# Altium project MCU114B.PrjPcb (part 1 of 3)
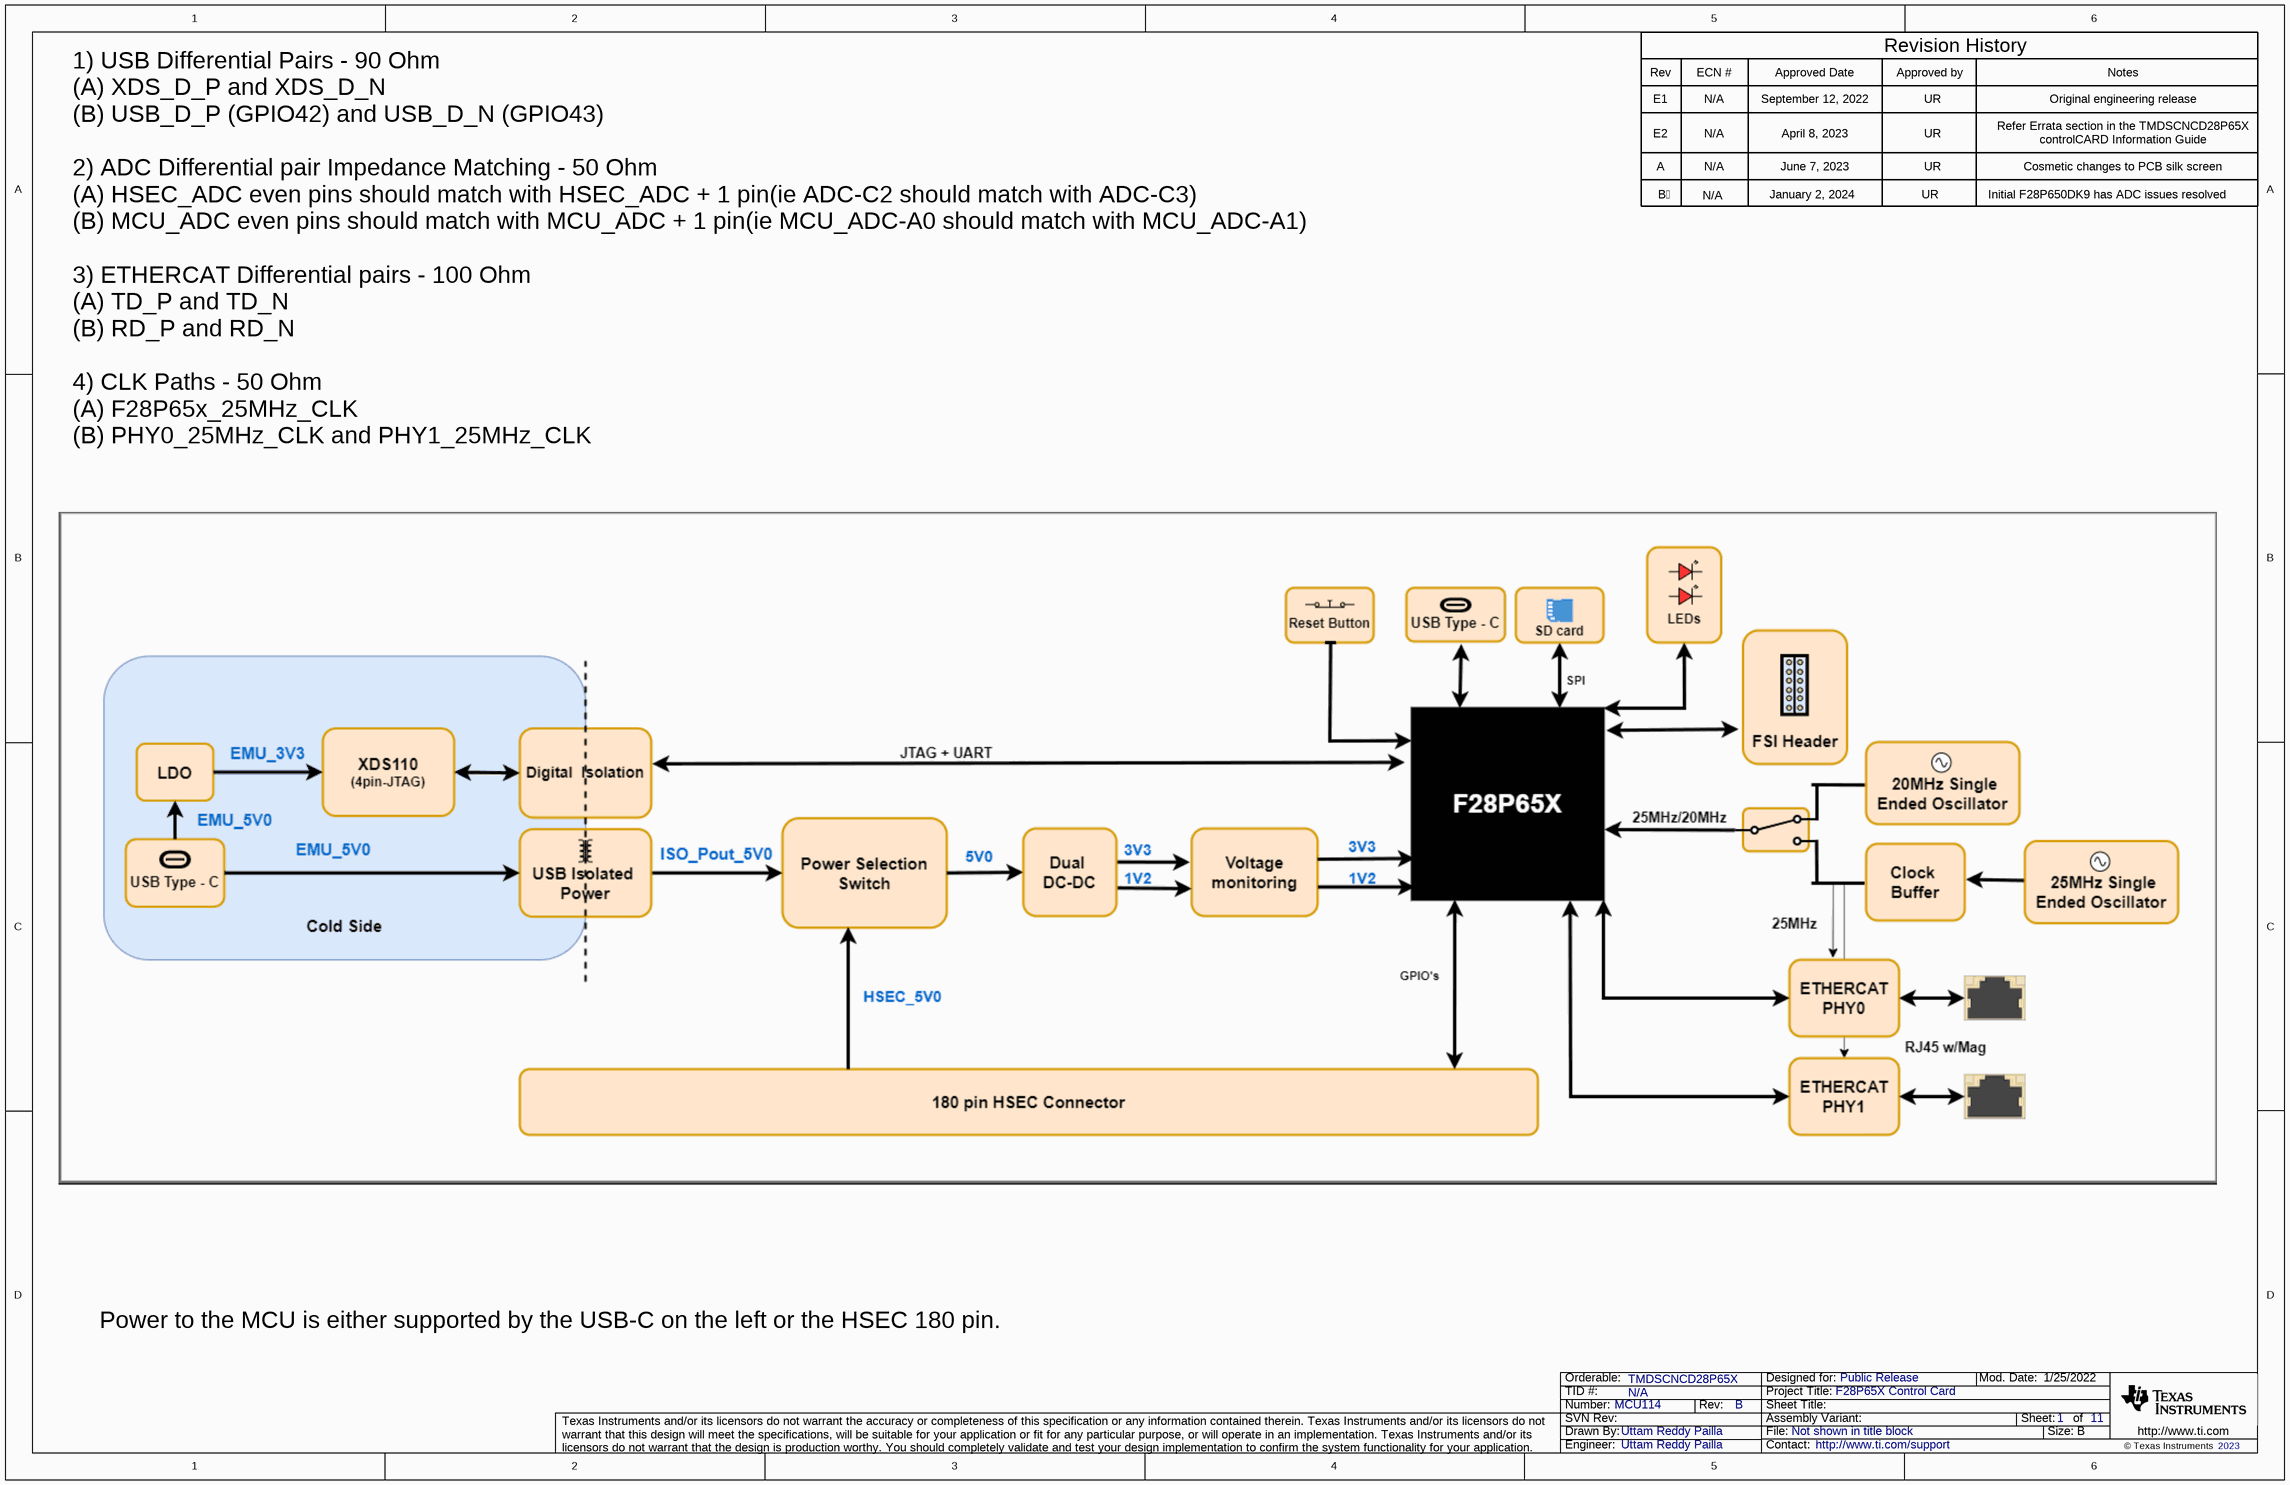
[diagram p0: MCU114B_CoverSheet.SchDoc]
CopyrightYear: 2023; DrawnBy: Uttam Reddy Pailla; EVM_orderable: TMDSCNCD28P65X; PCB_Layout: Uttam Reddy Pailla; PCB_Rev: B; PRJ_Customer: Public Release; PRJ_Engineer: Uttam Reddy Pailla; PRJ_Number: MCU114; PRJ_Title: F28P65X Control Card; SCH_Rev: B; TechSupport: http://www.ti.com/support; TID: N/A
11 sheets, 445 parts. Net scope: global (net labels, ports and power ports of the same name join across sheets).
Board file: MCU114B.PcbDoc
Sheets:
  MCU114B_CoverSheet.SchDoc
  MCU114B_GPIOs.SchDoc
  MCU114B_Support.SchDoc
  MCU114B_ADC.SchDoc
  MCU114B_Power.SchDoc
  MCU114B_EtherCAT.SchDoc
  MCU114B_USB.SchDoc
  MCU114B_XDS110_USB_Power.SchDoc
  MCU114B_XDS110_MCU.SchDoc
  MCU114B_Emulator_Interface.SchDoc
  MCU114B_EVM_Hardware.SchDoc

## Sheet MCU114B_CoverSheet.SchDoc
size 431 x 279 mm; Date: Not shown in title block; ApprovedBy: Not shown in title block; CheckedBy: Not shown in title block; Author: Not shown in title block; CompanyName: Not shown in title block; Engineer: Not shown in title block; Organization: Not shown in title block; Address1: Not shown in title block; Address2: Not shown in title block; Address3: Not shown in title block; Address4: Not shown in title block; DocumentNumber: 1; Revision: Use project parameter SCH_Rev; SheetNumber: 1; SheetTotal: 11; PageSetup: Record=PageOptions¦CenterHorizontal=True¦CenterVertical=True¦PrintScale=1.00¦XCorrection=1.00¦YCorrection=1.00¦PrintKind=0¦BorderSize=5000000¦LeftOffset=0¦BottomOffset=0¦Orientation=2¦PaperLength=1000¦PaperWidth=1000¦Scale=100¦PaperSource=15¦PrintQuality=600¦MediaType=1¦DitherType=10¦PaperKind=Letter¦PrintScaleMode=1

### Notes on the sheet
- Rev
- E1
- ECN #
- N/A
- Approved Date
- September 12, 2022
- Approved by
- UR
- Revision History
- Notes
- Original engineering release
- E2
- A
- April 8, 2023
- June 7, 2023
- Refer Errata section in the TMDSCNCD28P65X
- controlCARD Information Guide
- Cosmetic changes to PCB silk screen
- B
- January 2, 2024
- Initial F28P650DK9 has ADC issues resolved
- 1) USB Differential Pairs - 90 Ohm
  (A) XDS_D_P and XDS_D_N
  (B) USB_D_P (GPIO42) and USB_D_N (GPIO43)
  2) ADC Differential pair Impedance Matching - 50 Ohm
  (A) HSEC_ADC even pins should match with HSEC_ADC + 1 pin(ie ADC-C2 should match with ADC-C3)
  (B) MCU_ADC even pins should match with MCU_ADC + 1 pin(ie MCU_ADC-A0 should match with MCU_ADC-A1)
  3) ETHERCAT Differential pairs - 100 Ohm
  (A) TD_P and TD_N
  (B) RD_P and RD_N
  4) CLK Paths - 50 Ohm
  (A) F28P65x_25MHz_CLK
  (B) PHY0_25MHz_CLK and PHY1_25MHz_CLK
- Power to the MCU is either supported by the USB-C on the left or the HSEC 180 pin.

## Sheet MCU114B_GPIOs.SchDoc
size 431 x 279 mm; Date: Not shown in title block; ApprovedBy: Not shown in title block; CheckedBy: Not shown in title block; Author: Not shown in title block; CompanyName: Not shown in title block; Engineer: Not shown in title block; Organization: Not shown in title block; Address1: Not shown in title block; Address2: Not shown in title block; Address3: Not shown in title block; Address4: Not shown in title block; DocumentNumber: 2; Revision: Use project parameter SCH_Rev; SheetNumber: 2; SheetTotal: 11; PageSetup: Record=PageOptions¦CenterHorizontal=True¦CenterVertical=True¦PrintScale=1.00¦XCorrection=1.00¦YCorrection=1.00¦PrintKind=0¦BorderSize=5000000¦LeftOffset=0¦BottomOffset=0¦Orientation=2¦PaperLength=1000¦PaperWidth=1000¦Scale=100¦PaperSource=15¦PrintQuality=600¦MediaType=1¦DitherType=10¦PaperKind=Letter¦PrintScaleMode=1
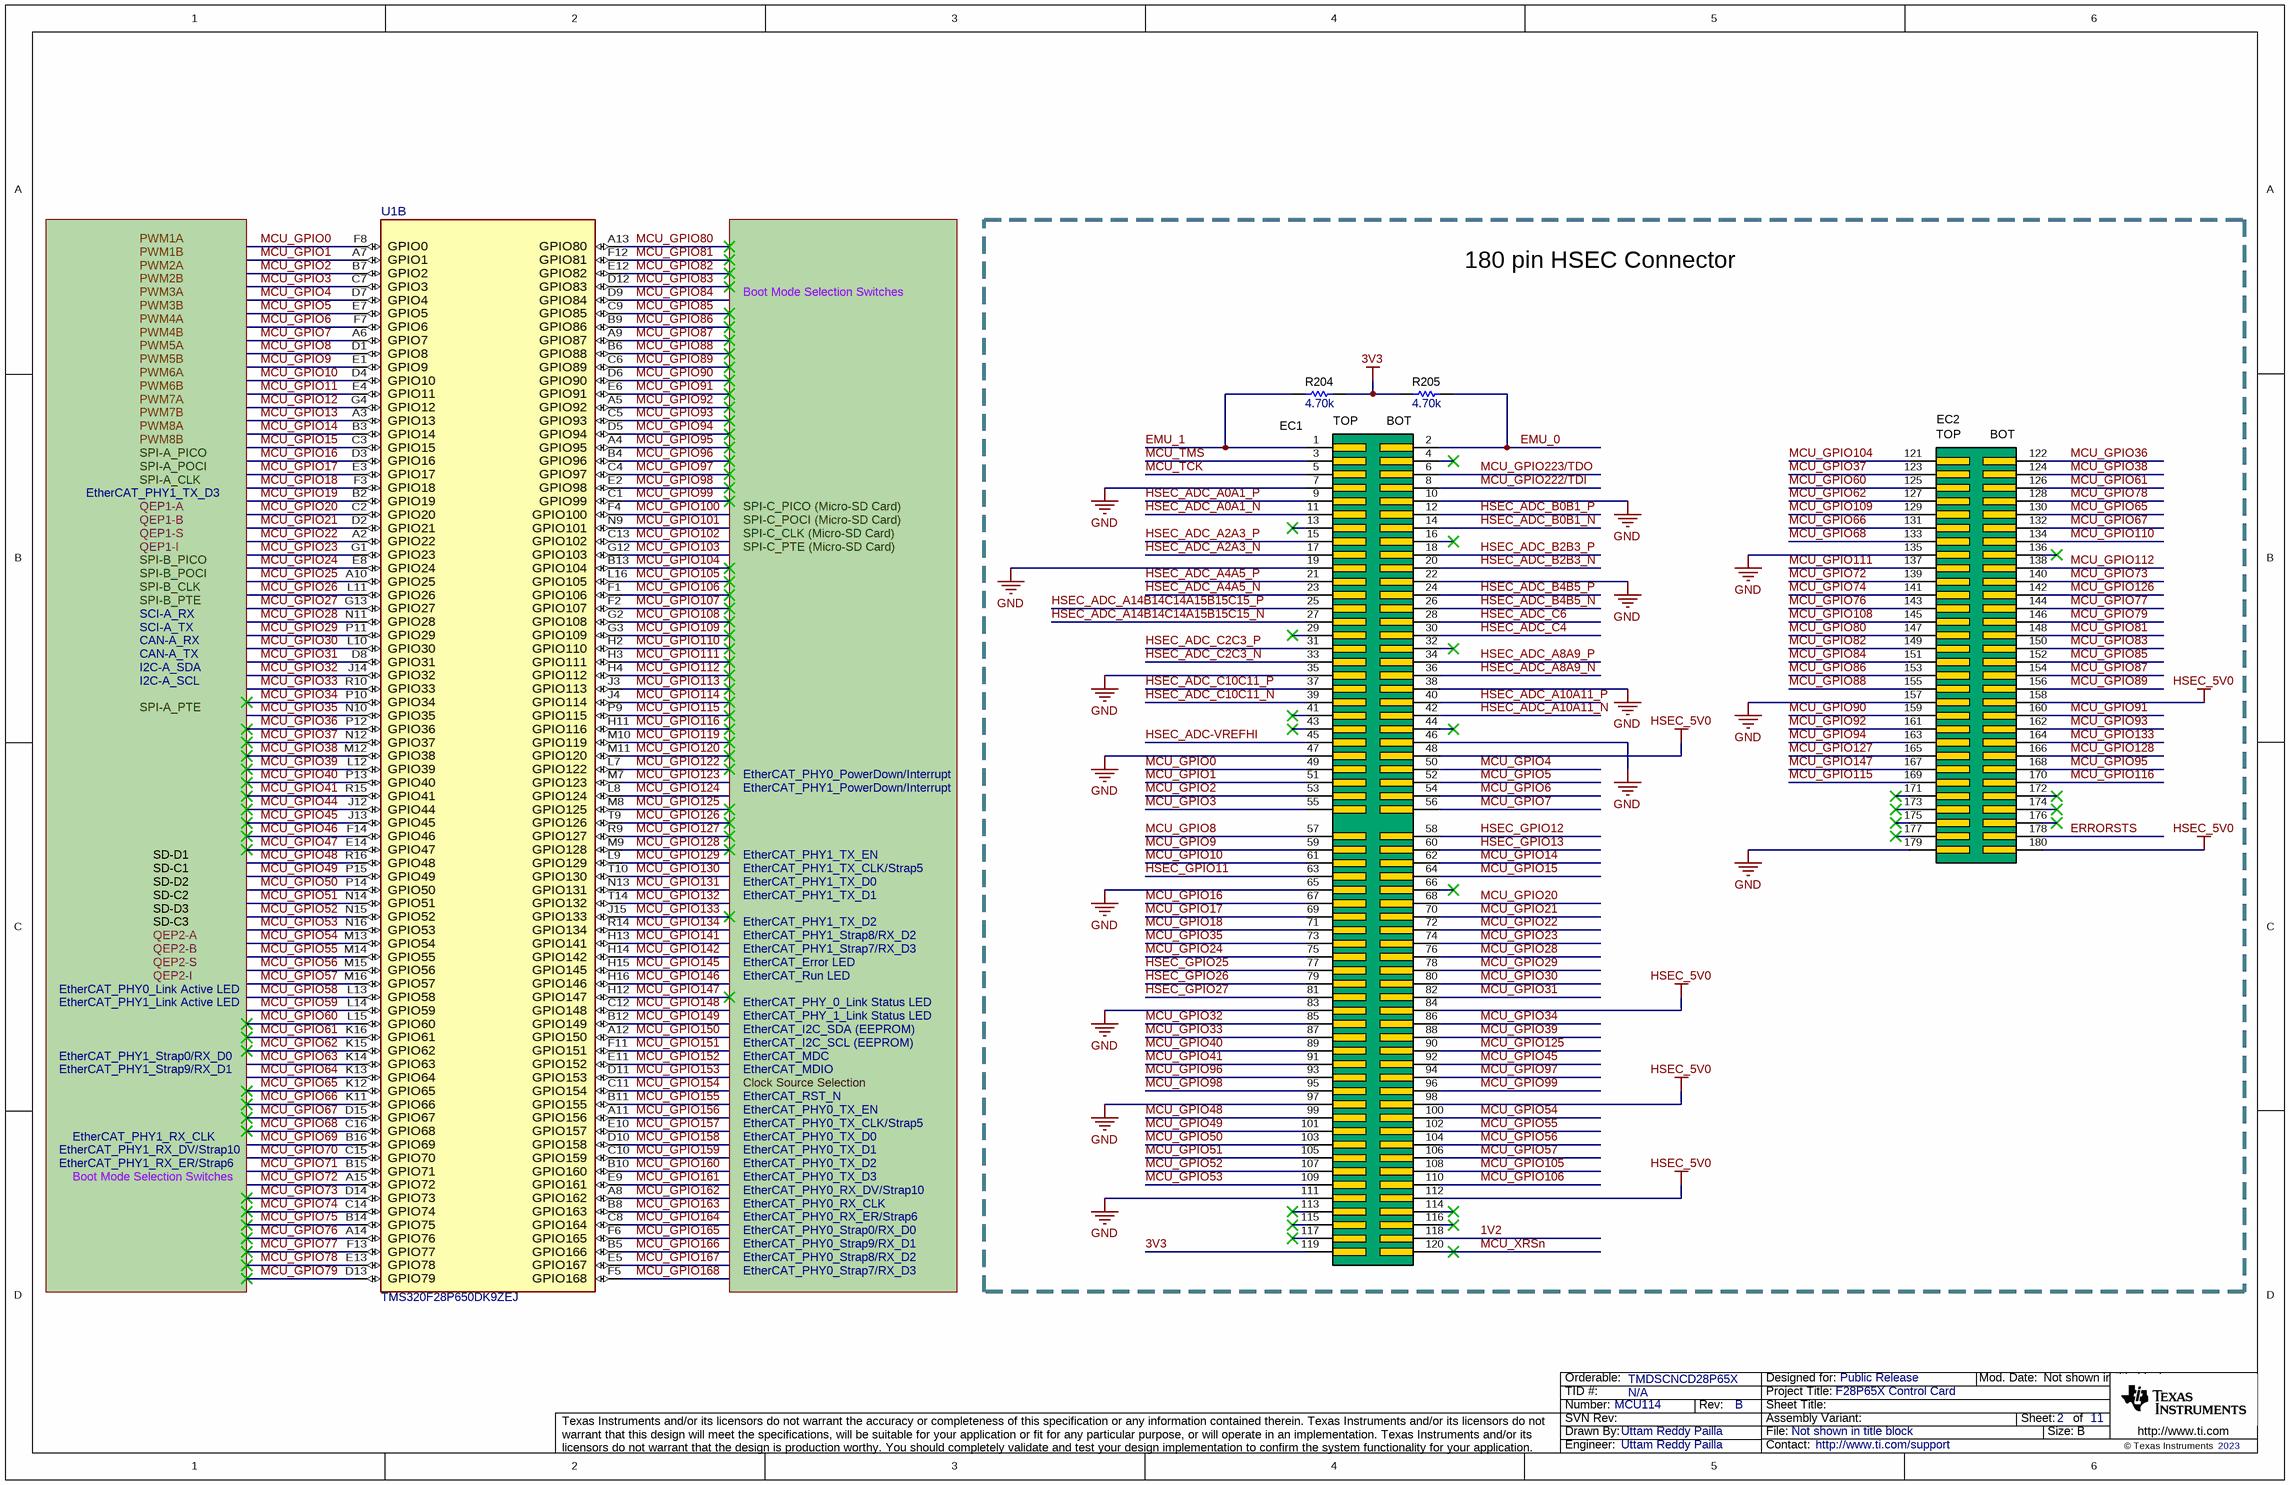
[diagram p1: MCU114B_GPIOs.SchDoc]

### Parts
EC1  controlCARD-120HSEC_Edge  [controlCARD-120HSEC_Edge]  (value not drawn)  (no BOM)
EC2  controlCARD-180HSEC-60pinAddon_Edge  [controlCARD-180HSEC-60pinAddon_Edge]  (value not drawn)  (no BOM)
R204  ValueDisplayed: 4.70k  [0402]  (hidden comment: CRG0402F4K7)
R205  ValueDisplayed: 4.70k  [0402]  (hidden comment: CRG0402F4K7)
U1  TMS320F28P650DK9ZEJ  [ZEJ0256A-MFG]  (part B of 4)

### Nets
1V2: EC1.118
3V3: EC1.119 R204.2 R205.1
GND: EC1.7 EC1.10 EC1.19 EC1.22 EC1.35 EC1.38 EC1.46 EC1.47 EC1.65 EC1.83 EC1.97 EC1.111 EC2.135 EC2.157 EC2.179
HSEC_5V0: EC1.48 EC1.84 EC1.98 EC1.112 EC2.158 EC2.180
EMU_0: EC1.2 R205.2
EMU_1: EC1.1 R204.1
ERRORSTS: EC2.178
HSEC_ADC-VREFHI: EC1.45
HSEC_ADC_A0A1_N: EC1.11
HSEC_ADC_A0A1_P: EC1.9
HSEC_ADC_A2A3_N: EC1.17
HSEC_ADC_A2A3_P: EC1.15
HSEC_ADC_A4A5_N: EC1.23
HSEC_ADC_A4A5_P: EC1.21
HSEC_ADC_A8A9_N: EC1.36
HSEC_ADC_A8A9_P: EC1.34
HSEC_ADC_A10A11_N: EC1.42
HSEC_ADC_A10A11_P: EC1.40
HSEC_ADC_A14B14C14A15B15C15_N: EC1.27
HSEC_ADC_A14B14C14A15B15C15_P: EC1.25
HSEC_ADC_B0B1_N: EC1.14
HSEC_ADC_B0B1_P: EC1.12
HSEC_ADC_B2B3_N: EC1.20
HSEC_ADC_B2B3_P: EC1.18
HSEC_ADC_B4B5_N: EC1.26
HSEC_ADC_B4B5_P: EC1.24
HSEC_ADC_C2C3_N: EC1.33
HSEC_ADC_C2C3_P: EC1.31
HSEC_ADC_C4: EC1.30
HSEC_ADC_C6: EC1.28
HSEC_ADC_C10C11_N: EC1.39
HSEC_ADC_C10C11_P: EC1.37
HSEC_GPIO11: EC1.63
HSEC_GPIO12: EC1.58
HSEC_GPIO13: EC1.60
HSEC_GPIO25: EC1.77
HSEC_GPIO26: EC1.79
HSEC_GPIO27: EC1.81
MCU_GPIO0: EC1.49 U1.F8(GPIO0)
MCU_GPIO1: EC1.51 U1.A7(GPIO1)
MCU_GPIO2: EC1.53 U1.B7(GPIO2)
MCU_GPIO3: EC1.55 U1.C7(GPIO3)
MCU_GPIO4: EC1.50 U1.D7(GPIO4)
MCU_GPIO5: EC1.52 U1.E7(GPIO5)
MCU_GPIO6: EC1.54 U1.F7(GPIO6)
MCU_GPIO7: EC1.56 U1.A6(GPIO7)
MCU_GPIO8: EC1.57 U1.D1(GPIO8)
MCU_GPIO9: EC1.59 U1.E1(GPIO9)
MCU_GPIO10: EC1.61 U1.D4(GPIO10)
MCU_GPIO11: U1.E4(GPIO11)
MCU_GPIO12: U1.G4(GPIO12)
MCU_GPIO13: U1.A3(GPIO13)
MCU_GPIO14: EC1.62 U1.B3(GPIO14)
MCU_GPIO15: EC1.64 U1.C3(GPIO15)
MCU_GPIO16: EC1.67 U1.D3(GPIO16)
MCU_GPIO17: EC1.69 U1.E3(GPIO17)
MCU_GPIO18: EC1.71 U1.F3(GPIO18)
MCU_GPIO19: U1.B2(GPIO19)
MCU_GPIO20: EC1.68 U1.C2(GPIO20)
MCU_GPIO21: EC1.70 U1.D2(GPIO21)
MCU_GPIO22: EC1.72 U1.A2(GPIO22)
MCU_GPIO23: EC1.74 U1.G1(GPIO23)
MCU_GPIO24: EC1.75 U1.E8(GPIO24)
MCU_GPIO25: U1.A10(GPIO25)
MCU_GPIO26: U1.L11(GPIO26)
MCU_GPIO27: U1.G13(GPIO27)
MCU_GPIO28: EC1.76 U1.N11(GPIO28)
MCU_GPIO29: EC1.78 U1.P11(GPIO29)
MCU_GPIO30: EC1.80 U1.L10(GPIO30)
MCU_GPIO31: EC1.82 U1.D8(GPIO31)
MCU_GPIO32: EC1.85 U1.J14(GPIO32)
MCU_GPIO33: EC1.87 U1.R10(GPIO33)
MCU_GPIO34: EC1.86 U1.P10(GPIO34)
MCU_GPIO35: EC1.73 U1.N10(GPIO35)
MCU_GPIO36: EC2.122 U1.P12(GPIO36)
MCU_GPIO37: EC2.123 U1.N12(GPIO37)
MCU_GPIO38: EC2.124 U1.M12(GPIO38)
MCU_GPIO39: EC1.88 U1.L12(GPIO39)
MCU_GPIO40: EC1.89 U1.P13(GPIO40)
MCU_GPIO41: EC1.91 U1.R15(GPIO41)
MCU_GPIO44: U1.J12(GPIO44)
MCU_GPIO45: EC1.92 U1.J13(GPIO45)
MCU_GPIO46: U1.F14(GPIO46)
MCU_GPIO47: U1.E14(GPIO47)
MCU_GPIO48: EC1.99 U1.R16(GPIO48)
MCU_GPIO49: EC1.101 U1.P15(GPIO49)
MCU_GPIO50: EC1.103 U1.P14(GPIO50)
MCU_GPIO51: EC1.105 U1.N14(GPIO51)
MCU_GPIO52: EC1.107 U1.N15(GPIO52)
MCU_GPIO53: EC1.109 U1.N16(GPIO53)
MCU_GPIO54: EC1.100 U1.M13(GPIO54)
MCU_GPIO55: EC1.102 U1.M14(GPIO55)
MCU_GPIO56: EC1.104 U1.M15(GPIO56)
MCU_GPIO57: EC1.106 U1.M16(GPIO57)
MCU_GPIO58: U1.L13(GPIO58)
MCU_GPIO59: U1.L14(GPIO59)
MCU_GPIO60: EC2.125 U1.L15(GPIO60)
MCU_GPIO61: EC2.126 U1.K16(GPIO61)
MCU_GPIO62: EC2.127 U1.K15(GPIO62)
MCU_GPIO63: U1.K14(GPIO63)
MCU_GPIO64: U1.K13(GPIO64)
MCU_GPIO65: EC2.130 U1.K12(GPIO65)
MCU_GPIO66: EC2.131 U1.K11(GPIO66)
MCU_GPIO67: EC2.132 U1.D15(GPIO67)
MCU_GPIO68: EC2.133 U1.C16(GPIO68)
MCU_GPIO69: U1.B16(GPIO69)
MCU_GPIO70: U1.C15(GPIO70)
MCU_GPIO71: U1.B15(GPIO71)
MCU_GPIO72: EC2.139 U1.A15(GPIO72)
MCU_GPIO73: EC2.140 U1.D14(GPIO73)
MCU_GPIO74: EC2.141 U1.C14(GPIO74)
MCU_GPIO75: U1.B14(GPIO75)
MCU_GPIO76: EC2.143 U1.A14(GPIO76)
MCU_GPIO77: EC2.144 U1.F13(GPIO77)
MCU_GPIO78: EC2.128 U1.E13(GPIO78)
MCU_GPIO79: EC2.146 U1.D13(GPIO79)
MCU_GPIO80: EC2.147 U1.A13(GPIO80)
MCU_GPIO81: EC2.148 U1.F12(GPIO81)
MCU_GPIO82: EC2.149 U1.E12(GPIO82)
MCU_GPIO83: EC2.150 U1.D12(GPIO83)
MCU_GPIO84: EC2.151 U1.D9(GPIO84)
MCU_GPIO85: EC2.152 U1.C9(GPIO85)
MCU_GPIO86: EC2.153 U1.B9(GPIO86)
MCU_GPIO87: EC2.154 U1.A9(GPIO87)
MCU_GPIO88: EC2.155 U1.B6(GPIO88)
MCU_GPIO89: EC2.156 U1.C6(GPIO89)
MCU_GPIO90: EC2.159 U1.D6(GPIO90)
MCU_GPIO91: EC2.160 U1.E6(GPIO91)
MCU_GPIO92: EC2.161 U1.A5(GPIO92)
MCU_GPIO93: EC2.162 U1.C5(GPIO93)
MCU_GPIO94: EC2.163 U1.D5(GPIO94)
MCU_GPIO95: EC2.168 U1.A4(GPIO95)
MCU_GPIO96: EC1.93 U1.B4(GPIO96)
MCU_GPIO97: EC1.94 U1.C4(GPIO97)
MCU_GPIO98: EC1.95 U1.E2(GPIO98)
MCU_GPIO99: EC1.96 U1.C1(GPIO99)
MCU_GPIO100: U1.F4(GPIO100)
MCU_GPIO101: U1.N9(GPIO101)
MCU_GPIO102: U1.C13(GPIO102)
MCU_GPIO103: U1.G12(GPIO103)
MCU_GPIO104: EC2.121 U1.B13(GPIO104)
MCU_GPIO105: EC1.108 U1.L16(GPIO105)
MCU_GPIO106: EC1.110 U1.F1(GPIO106)
MCU_GPIO107: U1.F2(GPIO107)
MCU_GPIO108: EC2.145 U1.G2(GPIO108)
MCU_GPIO109: EC2.129 U1.G3(GPIO109)
MCU_GPIO110: EC2.134 U1.H2(GPIO110)
MCU_GPIO111: EC2.137 U1.H3(GPIO111)
MCU_GPIO112: EC2.138 U1.H4(GPIO112)
MCU_GPIO113: U1.J3(GPIO113)
MCU_GPIO114: U1.J4(GPIO114)
MCU_GPIO115: EC2.169 U1.P9(GPIO115)
MCU_GPIO116: EC2.170 U1.H11(GPIO116)
MCU_GPIO119: U1.M10(GPIO119)
MCU_GPIO120: U1.M11(GPIO120)
MCU_GPIO122: U1.L7(GPIO122)
MCU_GPIO123: U1.M7(GPIO123)
MCU_GPIO124: U1.L8(GPIO124)
MCU_GPIO125: EC1.90 U1.M8(GPIO125)
MCU_GPIO126: EC2.142 U1.T9(GPIO126)
MCU_GPIO127: EC2.165 U1.R9(GPIO127)
MCU_GPIO128: EC2.166 U1.M9(GPIO128)
MCU_GPIO129: U1.L9(GPIO129)
MCU_GPIO130: U1.T10(GPIO130)
MCU_GPIO131: U1.N13(GPIO131)
MCU_GPIO132: U1.T14(GPIO132)
MCU_GPIO133: EC2.164 U1.J15(GPIO133)
MCU_GPIO134: U1.R14(GPIO134)
MCU_GPIO141: U1.H13(GPIO141)
MCU_GPIO142: U1.H14(GPIO142)
MCU_GPIO145: U1.H15(GPIO145)
MCU_GPIO146: U1.H16(GPIO146)
MCU_GPIO147: EC2.167 U1.H12(GPIO147)
MCU_GPIO148: U1.C12(GPIO148)
MCU_GPIO149: U1.B12(GPIO149)
MCU_GPIO150: U1.A12(GPIO150)
MCU_GPIO151: U1.F11(GPIO151)
MCU_GPIO152: U1.E11(GPIO152)
MCU_GPIO153: U1.D11(GPIO153)
MCU_GPIO154: U1.C11(GPIO154)
MCU_GPIO155: U1.B11(GPIO155)
MCU_GPIO156: U1.A11(GPIO156)
MCU_GPIO157: U1.E10(GPIO157)
MCU_GPIO158: U1.D10(GPIO158)
MCU_GPIO159: U1.C10(GPIO159)
MCU_GPIO160: U1.B10(GPIO160)
MCU_GPIO161: U1.E9(GPIO161)
MCU_GPIO162: U1.A8(GPIO162)
MCU_GPIO163: U1.B8(GPIO163)
MCU_GPIO164: U1.C8(GPIO164)
MCU_GPIO165: U1.F6(GPIO165)
MCU_GPIO166: U1.B5(GPIO166)
MCU_GPIO167: U1.E5(GPIO167)
MCU_GPIO168: U1.F5(GPIO168)
MCU_GPIO222/TDI: EC1.8
MCU_GPIO223/TDO: EC1.6
MCU_TCK: EC1.5
MCU_TMS: EC1.3
MCU_XRSn: EC1.120

Not connected (* = marked no-connect by the designer): EC1 4* 13* 16* 29* 32* 41* 43* 44* 66* 113* 114* 115* 116* 117*; EC2 136* 171* 172* 173* 174* 175* 176* 177*

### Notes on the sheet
- PWM1A
- PWM1B
- PWM2A
- PWM2B
- PWM3A
- Boot Mode Selection Switches
- 180 pin HSEC Connector
- PWM3B
- PWM4A
- PWM4B
- PWM5A
- PWM5B
- PWM6A
- PWM6B
- PWM7A
- PWM7B
- PWM8A
- EtherCAT_PHY1_TX_D3
- PWM8B
- SPI-A_PICO
- SPI-A_POCI
- SPI-A_CLK
- QEP1-A
- QEP1-B
- QEP1-S
- QEP1-I
- SPI-B_PICO
- SPI-C_PICO (Micro-SD Card)
- SPI-C_POCI (Micro-SD Card)
- SPI-C_CLK (Micro-SD Card)
- SPI-C_PTE (Micro-SD Card)
- SPI-B_POCI
- SPI-B_CLK
- SPI-B_PTE
- SCI-A_RX
- SCI-A_TX
- CAN-A_RX
- CAN-A_TX
- I2C-A_SDA
- I2C-A_SCL
- SPI-A_PTE
- EtherCAT_PHY0_PowerDown/Interrupt
- EtherCAT_PHY1_PowerDown/Interrupt
- SD-D1
- SD-C1
- SD-D2
- SD-C2
- EtherCAT_PHY1_TX_EN
- EtherCAT_PHY1_TX_CLK/Strap5
- EtherCAT_PHY1_TX_D0
- EtherCAT_PHY1_TX_D1
- SD-D3
- SD-C3
- QEP2-A
- QEP2-B
- QEP2-S
- EtherCAT_PHY1_TX_D2
- EtherCAT_PHY1_Strap8/RX_D2
- EtherCAT_PHY1_Strap7/RX_D3
- EtherCAT_Error LED
- EtherCAT_PHY0_Link Active LED
- EtherCAT_PHY1_Link Active LED
- QEP2-I
- EtherCAT_I2C_SDA (EEPROM)
- EtherCAT_Run LED
- EtherCAT_PHY_0_Link Status LED
- EtherCAT_PHY_1_Link Status LED
- EtherCAT_PHY1_Strap0/RX_D0
- EtherCAT_PHY1_Strap9/RX_D1
- EtherCAT_I2C_SCL (EEPROM)
- EtherCAT_MDC
- EtherCAT_MDIO
- Clock Source Selection
- EtherCAT_RST_N
- EtherCAT_PHY1_RX_ER/Strap6
- EtherCAT_PHY1_RX_DV/Strap10
- EtherCAT_PHY1_RX_CLK
- EtherCAT_PHY0_TX_EN
- EtherCAT_PHY0_TX_CLK/Strap5
- EtherCAT_PHY0_TX_D0
- EtherCAT_PHY0_TX_D1
- EtherCAT_PHY0_TX_D2
- EtherCAT_PHY0_TX_D3
- EtherCAT_PHY0_RX_DV/Strap10
- EtherCAT_PHY0_RX_ER/Strap6
- EtherCAT_PHY0_RX_CLK
- EtherCAT_PHY0_Strap0/RX_D0
- EtherCAT_PHY0_Strap9/RX_D1
- EtherCAT_PHY0_Strap8/RX_D2
- EtherCAT_PHY0_Strap7/RX_D3

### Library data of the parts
EC1 = CMP-0003813-3: C2000 controlCARD-120HSEC Edge Connector for Samtec HSEC8-160-01-L-DV-A-BL; Manufacturer: Any; Note: The pin numbering does not match Samtec datasheet
EC2 = CMP-0081961-1: C2000 controlCARD-180HSEC (60-pin addon) Edge connector for Samtec HSEC8-130-01-L-DV-A; Manufacturer: Any; Note: The pin numbering does not match Samtec datasheet
R204 R205 = CMP-0026631-1: RES, 4.70 k, 1%, 0.063 W, 0402; Manufacturer: TE Connectivity; Power_W: 63mW; TempCo: 100 ppm/C; Value_Code: 4k70; U/M: EA; Value: 4.70k; Res_ohm: 4.7k; SizeX_mm: 1; SizeY_mm: 0.5; SizeZ_mm: 0.6; Value2: 0.063W; AEC Qualified: N; AEC Category: Q200
U1 = CMP-0096042-2: Real-Time Microcontroller NFBGA256; Manufacturer: Texas Instruments; AEC Category: Q200; Core Architecture: C28x; Data Bus Width: 32bits; Number Of Ethernet Channels: 1; Number Of Cores: 2; CompType: IC; Number Of I/Os: 159; Interface: I2C,SPI,UART,CAN,USB,LIN,SCI,Ethernet,Other; Number Of Pwm Channels: 36; AEC Qualified: No; Number Of Timers/Counters: 6; Standoff Height: 0.35mm; Number Of Spi Channels: 4; SizeZ_mm: 1.4mm; Number Of Adc Channels: 40; Ram Size: 248KBytes; Frequency_Fixed: 200MHz; Memory Size: 1.28MBytes; Number Of A/D Converters: 3; Memory Type: FLASH

## Sheet MCU114B_Support.SchDoc
size 431 x 279 mm; Date: Not shown in title block; ApprovedBy: Not shown in title block; CheckedBy: Not shown in title block; Author: Not shown in title block; CompanyName: Not shown in title block; Engineer: Not shown in title block; Organization: Not shown in title block; Address1: Not shown in title block; Address2: Not shown in title block; Address3: Not shown in title block; Address4: Not shown in title block; DocumentNumber: 3; Revision: Use project parameter SCH_Rev; SheetNumber: 3; SheetTotal: 11; PageSetup: Record=PageOptions¦CenterHorizontal=True¦CenterVertical=True¦PrintScale=1.00¦XCorrection=1.00¦YCorrection=1.00¦PrintKind=0¦BorderSize=5000000¦LeftOffset=0¦BottomOffset=0¦Orientation=2¦PaperLength=1000¦PaperWidth=1000¦Scale=100¦PaperSource=15¦PrintQuality=600¦MediaType=1¦DitherType=10¦PaperKind=Letter¦PrintScaleMode=1
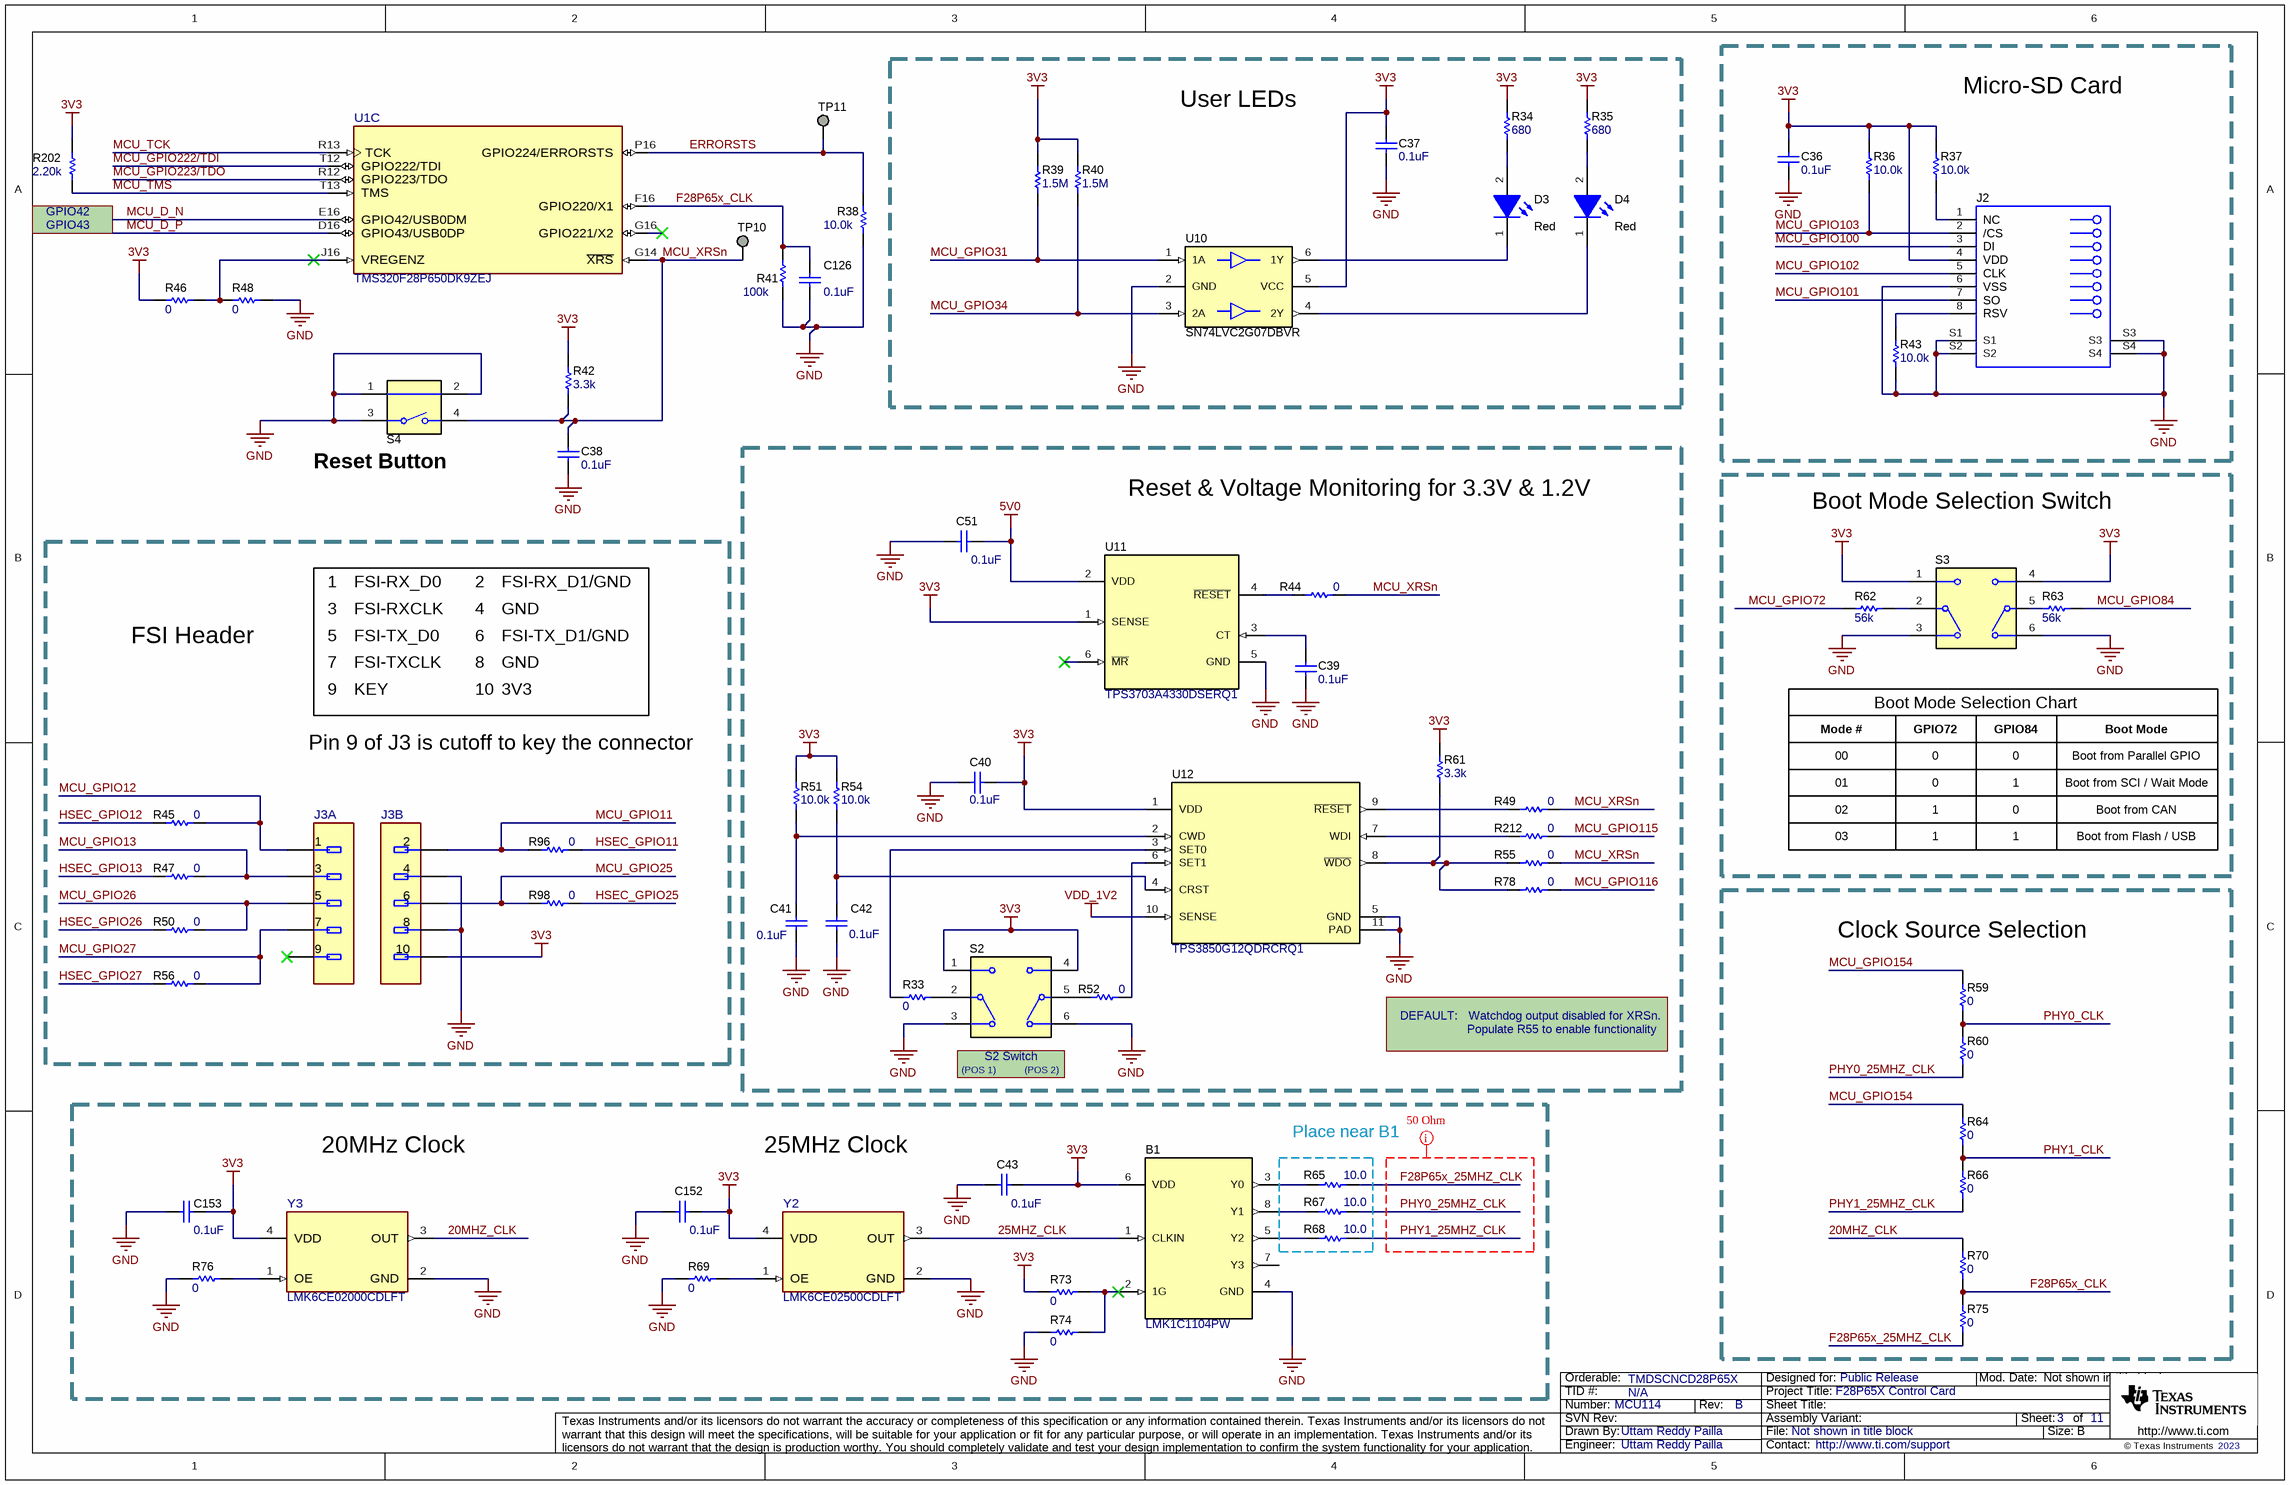
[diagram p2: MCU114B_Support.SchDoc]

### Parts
B1  LMK1C1104PW  [PW0008A_N]
C36  ValueDisplayed: 0.1uF  [0402]  (hidden comment: 885012205037)
C37  ValueDisplayed: 0.1uF  [0402]  (hidden comment: 885012205037)
C38  ValueDisplayed: 0.1uF  [0402]  (hidden comment: 885012205037)
C39  ValueDisplayed: 0.1uF  [0402]  (hidden comment: 885012205037)
C40  ValueDisplayed: 0.1uF  [0402]  (hidden comment: 885012205037)
C41  ValueDisplayed: 0.1uF  [0402]  (hidden comment: 885012205037)
C42  ValueDisplayed: 0.1uF  [0402]  (hidden comment: 885012205037)
C43  ValueDisplayed: 0.1uF  [0402]  (hidden comment: 885012205037)
C51  ValueDisplayed: 0.1uF  [0402]  (hidden comment: 885012205037)
C126  ValueDisplayed: 0.1uF  [0402]  (hidden comment: 885012205037)
C152  ValueDisplayed: 0.1uF  [0402]  (hidden comment: 885012205037)
C153  ValueDisplayed: 0.1uF  [0402]  (hidden comment: 885012205037)
D3  value Red  [WL-SMCW_RED_0805]  (hidden comment: 150080SS75000)
D4  value Red  [WL-SMCW_RED_0805]  (hidden comment: 150080SS75000)
J2  2908-05WB-MG  [3M_2908-05WB-MG]  (value not drawn)
J3  TMM-105-01-T-D  [FP-TMM-105-01-T-D_HDR10-MFG]  (value not drawn)  (parts A,B of 2)
R33  ValueDisplayed: 0  [0603]  (hidden comment: ERJ-3GEY0R00V)
R34  ValueDisplayed: 680  [0402]  (hidden comment: CRCW0402680RJNED)
R35  ValueDisplayed: 680  [0402]  (hidden comment: CRCW0402680RJNED)
R36  ValueDisplayed: 10.0k  [0402]  (hidden comment: AC0402FR-0710KL)
R37  ValueDisplayed: 10.0k  [0402]  (hidden comment: AC0402FR-0710KL)
R38  ValueDisplayed: 10.0k  [0402]  (hidden comment: AC0402FR-0710KL)
R39  ValueDisplayed: 1.5M  [0402]  (hidden comment: CRCW04021M50JNED)
R40  ValueDisplayed: 1.5M  [0402]  (hidden comment: CRCW04021M50JNED)
R41  ValueDisplayed: 100k  [0402]  (hidden comment: RG1005P-104-B-T5)
R42  ValueDisplayed: 3.3k  [0402]  (hidden comment: CRCW04023K30JNED)
R43  ValueDisplayed: 10.0k  [0402]  (hidden comment: AC0402FR-0710KL)
R44  ValueDisplayed: 0  [0603]  (hidden comment: ERJ-3GEY0R00V)
R45  ValueDisplayed: 0  [0603]  (hidden comment: ERJ-3GEY0R00V)
R46  ValueDisplayed: 0  [0402]  (hidden comment: ERJ-2GE0R00X)
R47  ValueDisplayed: 0  [0603]  (hidden comment: ERJ-3GEY0R00V)
R48  ValueDisplayed: 0  [0402]  (hidden comment: CRCW04020000Z0EDHP)
R49  ValueDisplayed: 0  [0603]  (hidden comment: ERJ-3GEY0R00V)
R50  ValueDisplayed: 0  [0603]  (hidden comment: ERJ-3GEY0R00V)
R51  ValueDisplayed: 10.0k  [0402]  (hidden comment: AC0402FR-0710KL)
R52  ValueDisplayed: 0  [0603]  (hidden comment: ERJ-3GEY0R00V)
R54  ValueDisplayed: 10.0k  [0402]  (hidden comment: AC0402FR-0710KL)
R55  ValueDisplayed: 0  [0603]  (hidden comment: ERJ-3GEY0R00V)
R56  ValueDisplayed: 0  [0603]  (hidden comment: ERJ-3GEY0R00V)
R59  ValueDisplayed: 0  [0603]  (hidden comment: ERJ-3GEY0R00V)
R60  ValueDisplayed: 0  [0603]  (hidden comment: ERJ-3GEY0R00V)
R61  ValueDisplayed: 3.3k  [0402]  (hidden comment: CRCW04023K30JNED)
R62  ValueDisplayed: 56k  [0402]  (hidden comment: CRCW040256K0JNED)
R63  ValueDisplayed: 56k  [0402]  (hidden comment: CRCW040256K0JNED)
R64  ValueDisplayed: 0  [0603]  (hidden comment: ERJ-3GEY0R00V)
R65  ValueDisplayed: 10.0  [CPF0402]  (hidden comment: CPF0402B10RE1)
R66  ValueDisplayed: 0  [0603]  (hidden comment: ERJ-3GEY0R00V)
R67  ValueDisplayed: 10.0  [CPF0402]  (hidden comment: CPF0402B10RE1)
R68  ValueDisplayed: 10.0  [CPF0402]  (hidden comment: CPF0402B10RE1)
R69  ValueDisplayed: 0  [0402]  (hidden comment: CRCW04020000Z0EDHP)
R70  ValueDisplayed: 0  [0603]  (hidden comment: ERJ-3GEY0R00V)
R73  ValueDisplayed: 0  [0402]  (hidden comment: ERJ-2GE0R00X)
R74  ValueDisplayed: 0  [0402]  (hidden comment: CRCW04020000Z0EDHP)
R75  ValueDisplayed: 0  [0603]  (hidden comment: ERJ-3GEY0R00V)
R76  ValueDisplayed: 0  [0402]  (hidden comment: CRCW04020000Z0EDHP)
R78  ValueDisplayed: 0  [0603]  (hidden comment: ERJ-3GEY0R00V)
R96  ValueDisplayed: 0  [0603]  (hidden comment: ERJ-3GEY0R00V)
R98  ValueDisplayed: 0  [0603]  (hidden comment: ERJ-3GEY0R00V)
R202  ValueDisplayed: 2.20k  [0402]  (hidden comment: CRCW04022K20FKED)
R212  ValueDisplayed: 0  [0603]  (hidden comment: ERJ-3GEY0R00V)
S2  CAS-D20TA  [SW_CAS-D20TA]  (value not drawn)
S3  CAS-D20TA  [SW_CAS-D20TA]  (value not drawn)
S4  1188E-1K2-V-TR  [SW_1188E]  (value not drawn)
TP10  TESTPOINT  [TP_50MIL-25MILHOLE]  (value not drawn)  (no BOM)
TP11  TESTPOINT  [TP_50MIL-25MILHOLE]  (value not drawn)  (no BOM)
U1  TMS320F28P650DK9ZEJ  [ZEJ0256A-MFG]  (part C of 4)
U10  SN74LVC2G07DBVR  [DBV0006A_N]
U11  TPS3703A4330DSERQ1  [DSE0006A]
U12  TPS3850G12QDRCRQ1  [DRC0010R]
Y2  LMK6CE02500CDLFT  [DLF0004A-MFG]
Y3  LMK6CE02000CDLFT  [DLF0004A-MFG]

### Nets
3V3: B1.6(VDD) C36.1 C37.1 C40.2 C43.1 C152.1 C153.1 J2.4(VDD) J3.10 R34.1 R35.1 R36.2 R37.2 R39.2 R40.2 R42.2 R46.1 R51.2 R54.2 R61.2 R73.1 R202.2 S2.1 S2.4 S3.1 S3.4 U10.5(VCC) U11.1(SENSE) U12.1(VDD) Y2.4(VDD) Y3.4(VDD)
5V0: C51.1 U11.2(VDD)
GND: B1.4(GND) C36.2 C37.2 C38.2 C39.2 C40.1 C41.1 C42.1 C43.2 C51.2 C126.1 C152.2 C153.2 J2.6(VSS) J2.S1 J2.S2 J2.S3 J2.S4 J3.4 J3.8 R38.1 R41.1 R43.1 R48.1 R69.2 R74.2 R76.2 S2.3 S2.6 S3.3 S3.6 S4.1 S4.2 S4.3 U10.2(GND) U11.5(GND) U12.5(GND) U12.11(PAD) Y2.2(GND) Y3.2(GND)
VDD_1V2: U12.10(SENSE)
20MHZ_CLK: R70.1 Y3.3(OUT)
25MHZ_CLK: B1.1(CLKIN) Y2.3(OUT)
ERRORSTS: R38.2 TP11.1 U1.P16(GPIO224/ERRORSTS)
F28P65x_25MHZ_CLK: R65.2 R75.2
F28P65x_CLK: C126.2 R41.2 R70.2 R75.1 U1.F16(GPIO220/X1)
HSEC_GPIO11: R96.1
HSEC_GPIO12: R45.2
HSEC_GPIO13: R47.2
HSEC_GPIO25: R98.1
HSEC_GPIO26: R50.2
HSEC_GPIO27: R56.2
MCU_D_N: U1.E16(GPIO42/USB0DM)
MCU_D_P: U1.D16(GPIO43/USB0DP)
MCU_GPIO11: J3.2 R96.2
MCU_GPIO12: J3.1 R45.1
MCU_GPIO13: J3.3 R47.1
MCU_GPIO25: J3.6 R98.2
MCU_GPIO26: J3.5 R50.1
MCU_GPIO27: J3.7 R56.1
MCU_GPIO31: R39.1 U10.1(1A)
MCU_GPIO34: R40.1 U10.3(2A)
MCU_GPIO72: R62.1
MCU_GPIO84: R63.1
MCU_GPIO100: J2.3(CMD)
MCU_GPIO101: J2.7(DAT0)
MCU_GPIO102: J2.5(CLK)
MCU_GPIO103: J2.2(CD/DAT3) R36.1
MCU_GPIO115: R212.1
MCU_GPIO116: R78.1
MCU_GPIO154: R59.1 R64.1
MCU_GPIO222/TDI: U1.T12(GPIO222/TDI)
MCU_GPIO223/TDO: U1.R12(GPIO223/TDO)
MCU_TCK: U1.R13(TCK)
MCU_TMS: R202.1 U1.T13(TMS)
MCU_XRSn: C38.1 R42.1 R44.1 R49.1 R55.1 S4.4 TP10.1 U1.G14(~{XRS})
PHY0_25MHZ_CLK: R60.2 R67.2
PHY0_CLK: R59.2 R60.1
PHY1_25MHZ_CLK: R66.2 R68.2
PHY1_CLK: R64.2 R66.1
NetB1_2: B1.2(1G) R73.2 R74.1
NetB1_3: B1.3(Y0) R65.1
NetB1_5: B1.5(Y2) R68.1
NetB1_8: B1.8(Y1) R67.1
NetC39_1: C39.1 U11.3(CT)
NetC41_2: C41.2 R51.1 U12.2(CWD)
NetC42_2: C42.2 R54.1 U12.4(CRST)
NetD3_1: D3.1(K) U10.6(1Y)
NetD3_2: D3.2(A) R34.2
NetD4_1: D4.1(K) U10.4(2Y)
NetD4_2: D4.2(A) R35.2
NetJ2_1: J2.1(DAT2) R37.1
NetJ2_8: J2.8(DAT1) R43.2
NetR33_1: R33.1 S2.2(C)
NetR33_2: R33.2 U12.3(SET0)
NetR44_2: R44.2 U11.4(~{RESET})
NetR46_2: R46.2 R48.2 U1.J16(VREGENZ)
NetR49_2: R49.2 U12.9(~{RESET})
NetR52_1: R52.1 U12.6(SET1)
NetR52_2: R52.2 S2.5(C)
NetR55_2: R55.2 R61.1 R78.2 U12.8(~{WDO})
NetR62_2: R62.2 S3.2(C)
NetR63_2: R63.2 S3.5(C)
NetR69_1: R69.1 Y2.1(OE)
NetR76_1: R76.1 Y3.1(OE)
NetR212_2: R212.2 U12.7(WDI)

Not connected (* = marked no-connect by the designer): B1 7(Y3); J3 9*; U1 G16(GPIO221/X2)*; U11 6(~{MR})*

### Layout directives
50 Ohm Impedance: Undefined: F28P65x_25MHZ_CLK, PHY0_25MHZ_CLK, PHY1_25MHZ_CLK

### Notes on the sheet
- User LEDs
- Micro-SD Card
- (near R202) GPIO42
- (near R202) GPIO43
- (near S4) Reset Button
- Reset & Voltage Monitoring for 3.3V & 1.2V
- Boot Mode Selection Switch
- FSI Header
- 1
- 3
- 5
- FSI-RX_D0
- FSI-RXCLK
- FSI-TX_D0
- 4
- 6
- 2
- FSI-RX_D1/GND
- FSI-TX_D1/GND
- GND
- 7
- 9
- FSI-TXCLK
- KEY
- 8
- 10
- 3V3
- Boot Mode Selection Chart
- Pin 9 of J3 is cutoff to key the connector
- Mode #
- 00
- GPIO72
- 0
- GPIO84
- Boot Mode
- Boot from Parallel GPIO
- 01
- 02
- 03
- Boot from SCI / Wait Mode
- Boot from CAN
- Boot from Flash / USB
- (near R59) Clock Source Selection
- DEFAULT:   Watchdog output disabled for XRSn.
- Populate R55 to enable functionality
- (near S2) (POS 1)
- (near S2) S2 Switch
- (near S2) (POS 2)
- 20MHz Clock
- 25MHz Clock
- Place near B1

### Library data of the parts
B1 = CMP-0860874-2: 3.3-V and 2.5-V LVCMOS High-Performance Clock Buffer Family, PW0008A (TSSOP-8); Alternate PartNumber: LMK1C1104PWR; Manufacturer: Texas Instruments; AEC Qualified: N; SizeZ_mm: 1.2; SizeY_mm: 3; SizeArea_mm2: 19.2; CompType: IC; SizeX_mm: 6.4; SizeAreaWB_mm2: 42; AEC Category: Q200
C36-C43 C51 C126 C152 C153 = CMP-0006228-2: CAP, CERM, 0.1 uF, 16 V, +/- 10%, X7R, 0402; Manufacturer: Wurth Elektronik; TaMin_C: -55°C; Polarized: N; SizeAreaWB_mm2: 3; Value1: Unknown; U/M: EA; Value: 0.1uF; TaMax_C: 125°C; SizeZ_mm: 0.6; SizeX_mm: 1; SizeY_mm: 0.5; Value2: 16V; Cap_F: 100nF; AEC Category: Q200
D3 = CMP-0002951-3: LED, Red, SMD; Manufacturer: Wurth Elektronik; Type: AlInGaP; Angle: 140; Vr_V: 5V; Ir_A: 25µA; Vf_V: 1.9V; Value1: 0.072W; Tjmax_C: 85°C; Io_A: 30mA; Power_TotalModule: 72mW
D4 = CMP-0002951-3: LED, Red, SMD; Manufacturer: Wurth Elektronik; Type: AlInGaP; Vf_V: 1.9V; Io_A: 30mA; Vr_V: 5V; Ir_A: 25µA; Tjmax_C: 85°C; Power_TotalModule: 72mW; Value1: 0.072W; Angle: 140
J2 = CMP-0075148-2: Connector, Micro SD, R/A, SMD; Manufacturer: 3M; Gender: Female; Row_Count: 1; Pitch_mm: 1.1; ContactFinish: Gold
J3 = CMP-0086568-1: Board-To-Board Connector, TMM Series, 10 Contacts, Header, 2 mm, Through Hole, 2 Rows; Manufacturer: Samtec; ContactFinish: Tin,Nickel; Voltage_V: 281V; Symbol Name: SYM-TMM-105-01-T-D; Row_Count: 2; Current_A: 3.2A
R33 R44 R45 R47 R49 R50 R52 R55 R56 R59 R60 R64 R66 R70 R75 R78 R96 R98 R212 = CMP-0025874-4: RES, 0, 5%, 0.1 W, AEC-Q200 Grade 0, 0603; Manufacturer: Panasonic; Power_W: 100mW; TempCo: 600 ppm/C; Value_Code: 0000; Value: 0; EIA_Code: E24; SizeX_mm: 1.6; SizeY_mm: 0.8; SizeZ_mm: 1; Value2: 0.1W; SizeArea_mm2: 1.28; AEC Qualified: Y; VDC_V: 50V; AEC Category: Q200; SizeAreaWB_mm2: 4.68
R34 R35 = CMP-0026962-3: RES, 680, 5%, 0.063 W, AEC-Q200 Grade 0, 0402; Manufacturer: Vishay-Dale; Value: 680; Value_Code: 680R; Power_W: 63mW; Value2: 0.063W; VDC_V: 50V; TempCo: 200 ppm/C; EIA_Code: E24; AEC Category: Q200; AEC Qualified: Y; AEC Grade: 0; SizeArea_mm2: 0.5; SizeX_mm: 1; SizeZ_mm: 0.6
R36-R38 R43 R51 R54 = CMP-0077731-1: RES, 10.0 k, 1%, 0.063 W, AEC-Q200 Grade 0, 0402; Manufacturer: Yageo America; Power_W: 63mW; TempCo: 100 ppm/C; Value_Code: 10k0; U/M: EA; Value: 10.0k; EIA_Code: E96; Res_ohm: 10k; SizeX_mm: 1.0; SizeY_mm: 0.5; SizeZ_mm: 0.6; Value2: 0.063W; AEC Qualified: Y; VDC_V: 50V; AEC Grade: 0; AEC Category: Q200
R39 R40 = CMP-0026863-2: RES, 1.5 M, 5%, 0.063 W, AEC-Q200 Grade 0, 0402; Manufacturer: Vishay-Dale; Power_W: 63mW; TempCo: 200 ppm/C; Value_Code: 1M50; Value: 1.5Meg; EIA_Code: E24; SizeX_mm: 1; SizeY_mm: 0.5; SizeZ_mm: 0.6; Value2: 0.063W; AEC Qualified: Y; VDC_V: 50V; AEC Category: Q200; AEC Grade: 0
R41 = CMP-0026815-1: RES, 100 k, 0.1%, 0.063 W, 0402; Manufacturer: Susumu Co Ltd; Power_W: 63mW; TempCo: 25 ppm/C; U/M: EA; Value: 100k; EIA_Code: E192; SizeX_mm: 1; SizeY_mm: 0.5; SizeZ_mm: 0.6; Value2: 0.063W; AEC Category: Q200
R42 R61 = CMP-0026918-5: RES, 3.3 k, 5%, 0.063 W, AEC-Q200 Grade 0, 0402; Manufacturer: Vishay-Dale; Power_W: 63mW; TempCo: 200 ppm/C; Value_Code: 3k30; Value: 3.3k; EIA_Code: E24; SizeX_mm: 1; SizeY_mm: 0.5; SizeZ_mm: 0.6; Value2: 0.063W; AEC Qualified: Y; VDC_V: 50V; AEC Category: Q200; AEC Grade: 0
R46 R73 = CMP-0026992-3: RES, 0, 5%, 0.1 W, AEC-Q200 Grade 0, 0402; Manufacturer: Panasonic; Power_W: 100mW; TempCo: 600 ppm/C; Value_Code: 0000; Value: 0; EIA_Code: E24; SizeX_mm: 1; SizeY_mm: 0.5; SizeZ_mm: 0.6; Value2: 0.1W; AEC Qualified: Y; VDC_V: 50V; AEC Category: Q200; SizeAreaWB_mm2: 3
R48 R69 R74 R76 = CMP-0081856-1: RES, 0, 0%, 0.2 W, AEC-Q200 Grade 0, 0402; Manufacturer: Vishay-Dale; SizeAreaWB_mm2: 3; SizeArea_mm2: 0.5; AEC Qualified: Y; AEC Category: Q200; Value: 0; SizeZ_mm: 0.6; Power_W: 200mW; VDC_V: 50V; Value2: 0.2W; SizeX_mm: 1
R62 R63 = CMP-0026949-3: RES, 56 k, 5%, 0.063 W, AEC-Q200 Grade 0, 0402; Manufacturer: Vishay-Dale; Value: 56k; Value_Code: 56k0; Power_W: 63mW; Value2: 0.063W; VDC_V: 50V; TempCo: 200 ppm/C; EIA_Code: E24; AEC Category: Q200; AEC Qualified: Y; AEC Grade: 0; SizeArea_mm2: 0.5; SizeX_mm: 1; SizeZ_mm: 0.6
R65 R67 R68 = CMP-0026765-1: RES, 10.0, 0.1%, 0.063 W, 0402; Manufacturer: TE Connectivity; Power_W: 63mW; TempCo: 25 ppm/C; Value_Code: 10R0; U/M: EA; Value: 10.0; EIA_Code: E192; Res_ohm: 10; SizeX_mm: 1; SizeY_mm: 0.5; SizeZ_mm: 0.35; Value2: 0.063W; AEC Qualified: N; AEC Category: Q200
R202 = CMP-0026231-2: RES, 2.20 k, 1%, 0.063 W, AEC-Q200 Grade 0, 0402; Manufacturer: Vishay-Dale; Power_W: 63mW; TempCo: 100 ppm/C; Value_Code: 2k20; Value: 2.20k; Res_ohm: 2.2k; SizeX_mm: 1; SizeY_mm: 0.5; SizeZ_mm: 0.6; Value2: 0.063W; AEC Qualified: Y; AEC Category: Q200; AEC Grade: 0
S2 S3 = CMP-0002233-1: Switch, Dual SPDT,  2 Pos, 0.1A, 6VDC, SMD; Manufacturer: Copal Electronics; CurrentRating_mA: 100A; SwitchFunction: On-On; VDC_V: 6V; PositionCount: 2
S4 = CMP-0002328-1: Switch, SPST, 0.05 A, 12 VDC, SMD; Manufacturer: Diptronics; SizeAreaWB_mm2: 53.9; SizeArea_mm2: 27.3; SizeX_mm: 7.8; SizeY_mm: 3.5; VDC_V: 12V; PositionCount: 1; CurrentRating_mA: 50A
TP10 TP11 = CMP-0078143-3: TEST POINT.  No entry in BOM.
U1 = CMP-0096042-2: as U1 on sheet MCU114B_GPIOs
U10 = CMP-0051789-2: Dual Buffer/Driver with Open-Drain Output, DBV0006A, LARGE T&R; Manufacturer: Texas Instruments; 3-State Output: No; Bits(#): 2; F @ Nom Voltage(Max)(Mhz): 150; ICC @ Nom Voltage(Max)(mA): 0.01; Input Type: CMOS/TTL; Logic: True; Output Drive (IOL/IOH)(Max)(mA): 32/-32; Output Type: CMOS; Rating: Catalog; Sub-Family: Inverting Buffer/Driver; Technology Family: LVC; tpd @ Nom Voltage(Max)(ns): 8.6,4.4,3.7,2.9; VCC(Max)(V): 5.5; VCC(Min)(V): 1.65; Voltage(Nom)(V): 1.8,2.5,3.3,5; AEC Category: Q200; AEC Qualified: N; CompType: IC; Green_Lifecycle: Active; Green_REACh: Passed; SizeArea_mm2: 8.12; SizeAreaWB_mm2: 14.82; SizeX_mm: 2.8; SizeY_mm: 2.9; SizeZ_mm: 1.45
U11 = CMP-0750051-1: Overvoltage and Undervoltage Reset IC With Time Delay and Manual Reset, DSE0006A (WSON-6); Alternate Manufacturer: Texas Instruments; AEC Category: Q200; SizeY_mm: 1.5; AEC Qualified: Y; SizeAreaWB_mm2: 6.25; SizeZ_mm: 0.8; SizeArea_mm2: 2.25
U12 = CMP-0081428-2: Automotive Precision Voltage Supervisor With Programmable Window Watchdog Timer, DRC0010R (VSON-10); Alternate Manufacturer: Texas Instruments; SizeAreaWB_mm2: 16; SizeZ_mm: 1; SizeX_mm: 3; SizeArea_mm2: 9; CompType: IC; AEC Qualified: Y; AEC Category: Q200
Y2 = CMP-0096024-2: High-Performance BAW Oscillator; Manufacturer: Texas Instruments; Load Capacitance: 30pF; TJmax_C: +125°C; Frequency Stability: 25ppm; SizeZ_mm: 1mm; Max Supply Current: 50mA; Min Supply Voltage: 2.375V; Standoff Height: 0mm; Frequency_Fixed: 25MHz; Max Supply Voltage: 3.465V; TaMax_C: +105°C; AEC Qualified: No; TaMin_C: -40°C; AEC Category: Q200; CompType: IC
Y3 = CMP-0096023-2: High-Performance BAW Oscillator 20MHz 2.5V-3.3V ±5% VSON4; Manufacturer: Texas Instruments; TJmax_C: +125°C; Frequency Stability: 25ppm; SizeZ_mm: 1mm; Min Supply Voltage: 2.375V; TaMin_C: -40°C; Max Supply Voltage: 3.465V; Standoff Height: 0mm; TaMax_C: +105°C; Load Capacitance: 30pF; Max Supply Current: 50mA; AEC Qualified: No; AEC Category: Q200; CompType: IC

## Sheet MCU114B_ADC.SchDoc
size 431 x 279 mm; Date: Not shown in title block; ApprovedBy: Not shown in title block; CheckedBy: Not shown in title block; Author: Not shown in title block; CompanyName: Not shown in title block; Engineer: Not shown in title block; Organization: Not shown in title block; Address1: Not shown in title block; Address2: Not shown in title block; Address3: Not shown in title block; Address4: Not shown in title block; DocumentNumber: 4; Revision: Use project parameter SCH_Rev; SheetNumber: 4; SheetTotal: 11; PageSetup: Record=PageOptions¦CenterHorizontal=True¦CenterVertical=True¦PrintScale=1.00¦XCorrection=1.00¦YCorrection=1.00¦PrintKind=0¦BorderSize=5000000¦LeftOffset=0¦BottomOffset=0¦Orientation=2¦PaperLength=1000¦PaperWidth=1000¦Scale=100¦PaperSource=15¦PrintQuality=600¦MediaType=1¦DitherType=10¦PaperKind=Letter¦PrintScaleMode=1
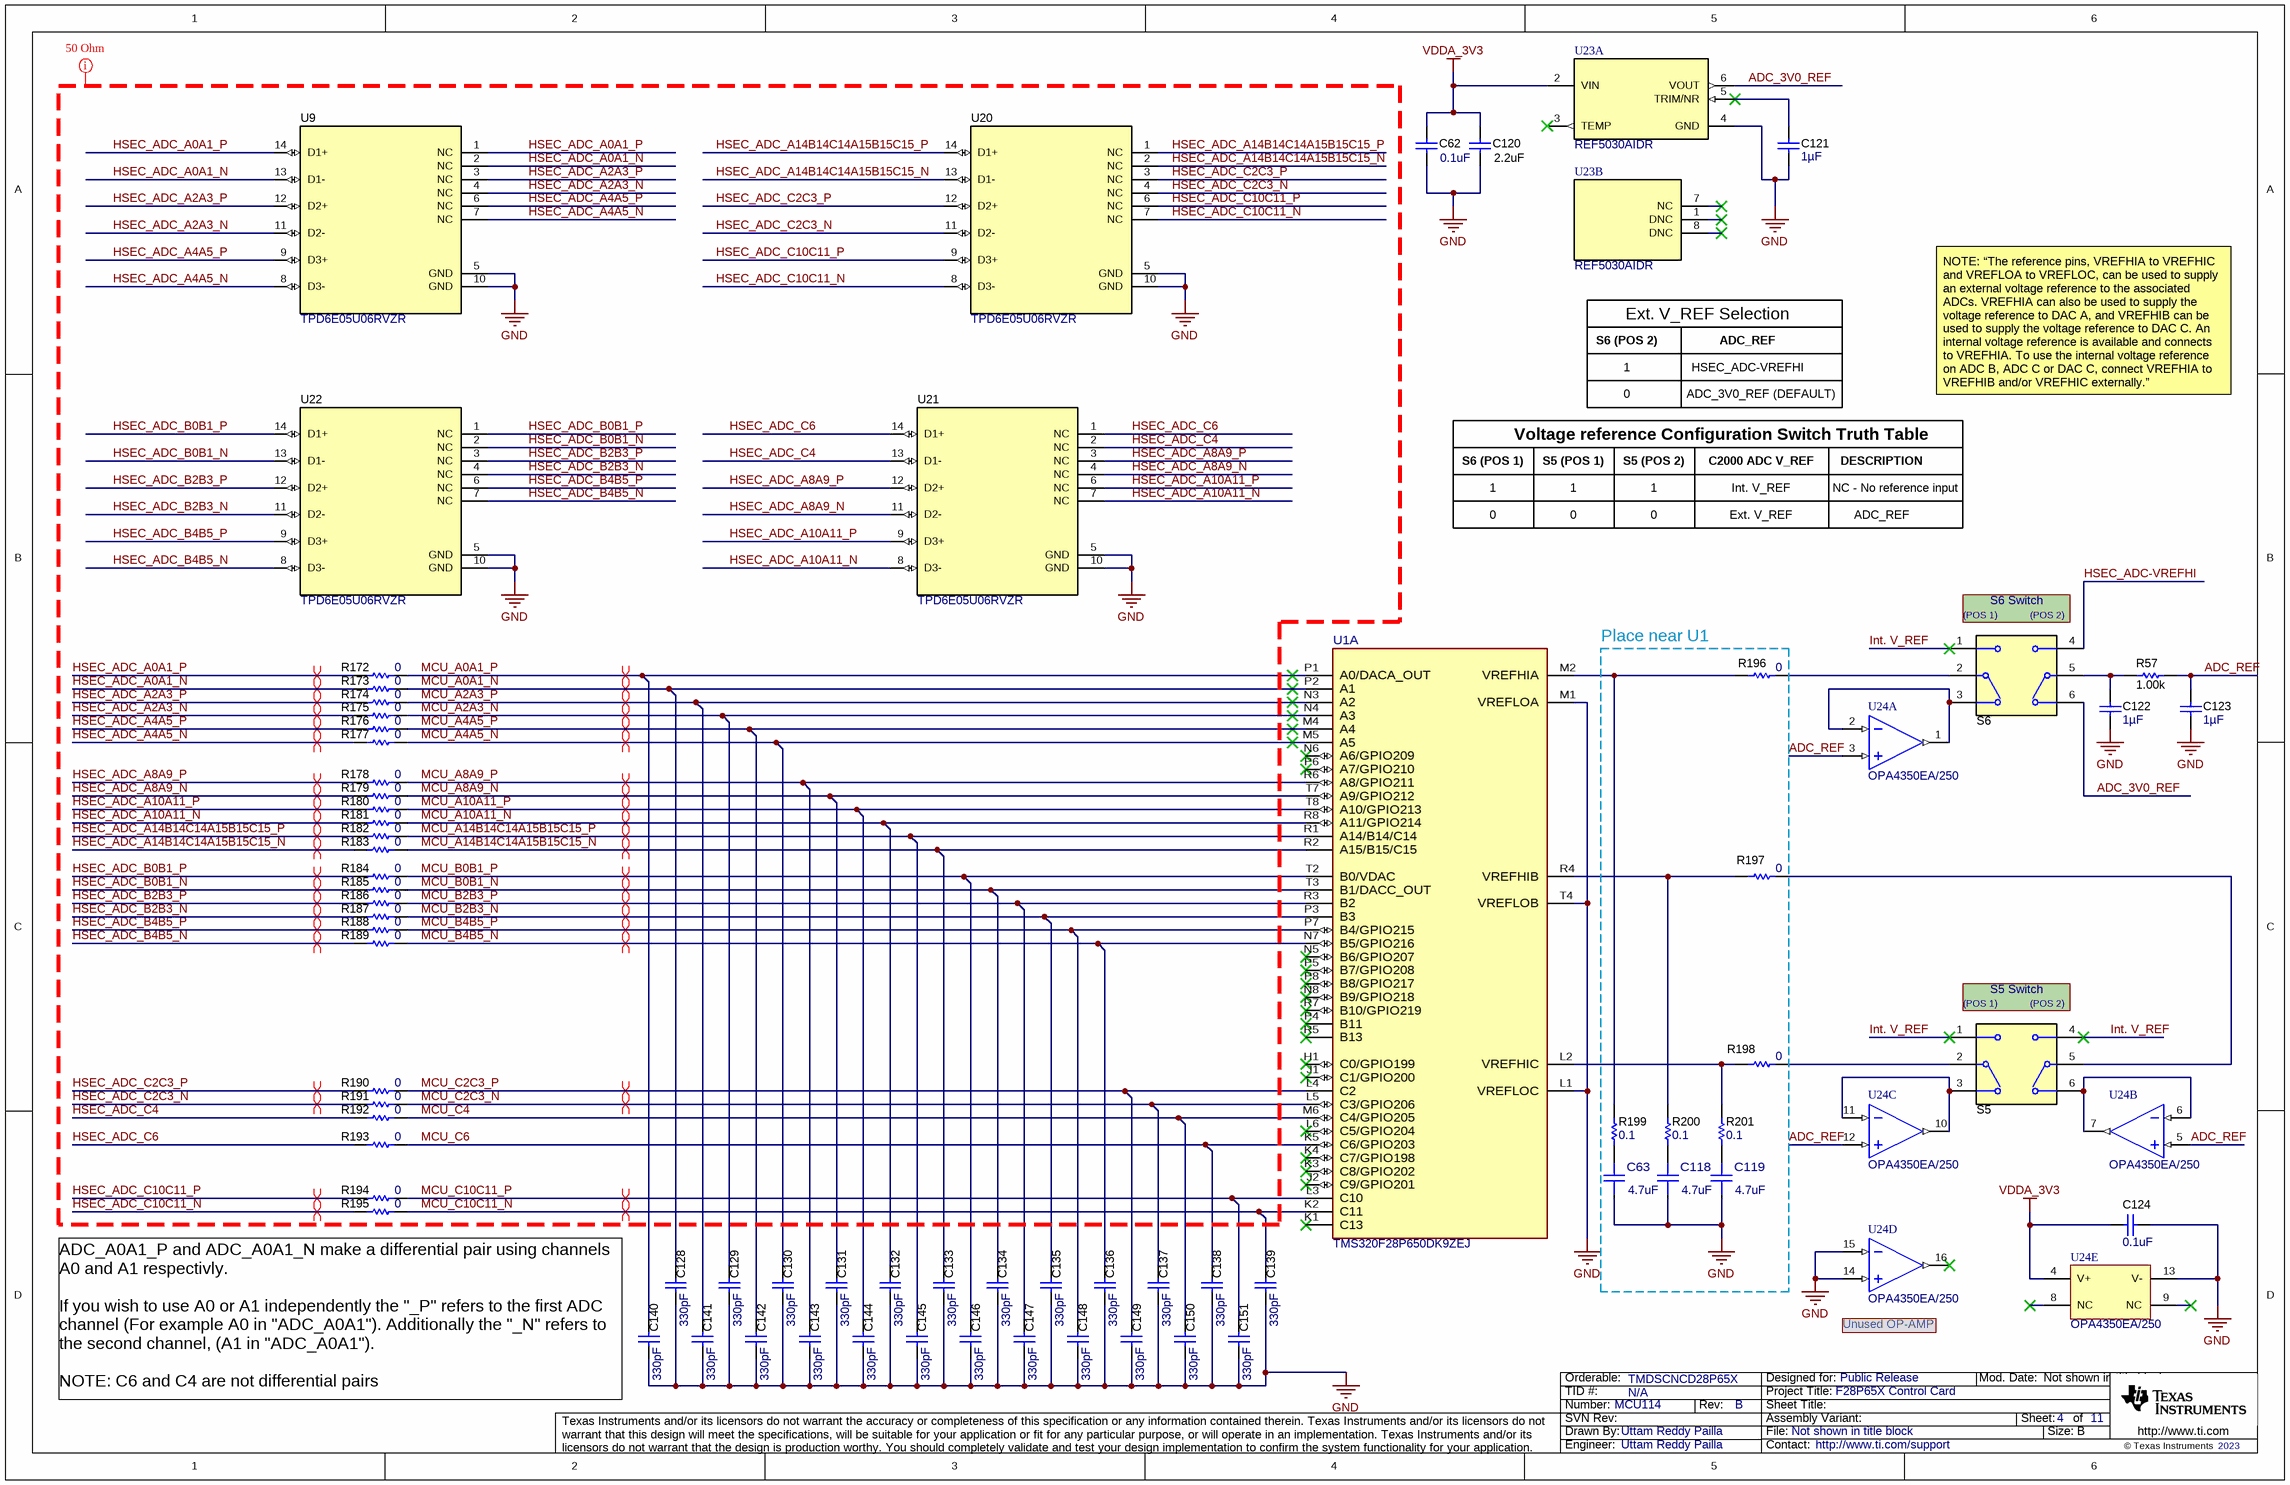
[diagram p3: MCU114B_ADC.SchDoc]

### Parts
C62  Cap_F: 0.1uF  [0603]  (hidden comment: 885012206046)
C63  ValueDisplayed: 4.7uF  [FP-885012106012_0603-MFG]  (hidden comment: 885012106012)
C118  ValueDisplayed: 4.7uF  [FP-885012106012_0603-MFG]  (hidden comment: 885012106012)
C119  ValueDisplayed: 4.7uF  [FP-885012106012_0603-MFG]  (hidden comment: 885012106012)
C120  ValueDisplayed: 2.2uF  [0603]  (hidden comment: 885012106018)
C121  Cap_F: 1µF  [0603]  (hidden comment: 885012206052)
C122  Cap_F: 1µF  [0603]  (hidden comment: 885012206052)
C123  Cap_F: 1µF  [0603]  (hidden comment: 885012206052)
C124  Cap_F: 0.1uF  [0603]  (hidden comment: 885012206046)
C128  ValueDisplayed: 330pF  [0603]  (hidden comment: C0603C331J5GACTU)
C129  ValueDisplayed: 330pF  [0603]  (hidden comment: C0603C331J5GACTU)
C130  ValueDisplayed: 330pF  [0603]  (hidden comment: C0603C331J5GACTU)
C131  ValueDisplayed: 330pF  [0603]  (hidden comment: C0603C331J5GACTU)
C132  ValueDisplayed: 330pF  [0603]  (hidden comment: C0603C331J5GACTU)
C133  ValueDisplayed: 330pF  [0603]  (hidden comment: C0603C331J5GACTU)
C134  ValueDisplayed: 330pF  [0603]  (hidden comment: C0603C331J5GACTU)
C135  ValueDisplayed: 330pF  [0603]  (hidden comment: C0603C331J5GACTU)
C136  ValueDisplayed: 330pF  [0603]  (hidden comment: C0603C331J5GACTU)
C137  ValueDisplayed: 330pF  [0603]  (hidden comment: C0603C331J5GACTU)
C138  ValueDisplayed: 330pF  [0603]  (hidden comment: C0603C331J5GACTU)
C139  ValueDisplayed: 330pF  [0603]  (hidden comment: C0603C331J5GACTU)
C140  ValueDisplayed: 330pF  [0603]  (hidden comment: C0603C331J5GACTU)
C141  ValueDisplayed: 330pF  [0603]  (hidden comment: C0603C331J5GACTU)
C142  ValueDisplayed: 330pF  [0603]  (hidden comment: C0603C331J5GACTU)
C143  ValueDisplayed: 330pF  [0603]  (hidden comment: C0603C331J5GACTU)
C144  ValueDisplayed: 330pF  [0603]  (hidden comment: C0603C331J5GACTU)
C145  ValueDisplayed: 330pF  [0603]  (hidden comment: C0603C331J5GACTU)
C146  ValueDisplayed: 330pF  [0603]  (hidden comment: C0603C331J5GACTU)
C147  ValueDisplayed: 330pF  [0603]  (hidden comment: C0603C331J5GACTU)
C148  ValueDisplayed: 330pF  [0603]  (hidden comment: C0603C331J5GACTU)
C149  ValueDisplayed: 330pF  [0603]  (hidden comment: C0603C331J5GACTU)
C150  ValueDisplayed: 330pF  [0603]  (hidden comment: C0603C331J5GACTU)
C151  ValueDisplayed: 330pF  [0603]  (hidden comment: C0603C331J5GACTU)
R57  ValueDisplayed: 1.00k  [0603]  (hidden comment: RC0603FR-071KL)
R172  ValueDisplayed: 0  [0603]  (hidden comment: ERJ-3GEY0R00V)
R173  ValueDisplayed: 0  [0603]  (hidden comment: ERJ-3GEY0R00V)
R174  ValueDisplayed: 0  [0603]  (hidden comment: ERJ-3GEY0R00V)
R175  ValueDisplayed: 0  [0603]  (hidden comment: ERJ-3GEY0R00V)
R176  ValueDisplayed: 0  [0603]  (hidden comment: ERJ-3GEY0R00V)
R177  ValueDisplayed: 0  [0603]  (hidden comment: ERJ-3GEY0R00V)
R178  ValueDisplayed: 0  [0603]  (hidden comment: ERJ-3GEY0R00V)
R179  ValueDisplayed: 0  [0603]  (hidden comment: ERJ-3GEY0R00V)
R180  ValueDisplayed: 0  [0603]  (hidden comment: ERJ-3GEY0R00V)
R181  ValueDisplayed: 0  [0603]  (hidden comment: ERJ-3GEY0R00V)
R182  ValueDisplayed: 0  [0603]  (hidden comment: ERJ-3GEY0R00V)
R183  ValueDisplayed: 0  [0603]  (hidden comment: ERJ-3GEY0R00V)
R184  ValueDisplayed: 0  [0603]  (hidden comment: ERJ-3GEY0R00V)
R185  ValueDisplayed: 0  [0603]  (hidden comment: ERJ-3GEY0R00V)
R186  ValueDisplayed: 0  [0603]  (hidden comment: ERJ-3GEY0R00V)
R187  ValueDisplayed: 0  [0603]  (hidden comment: ERJ-3GEY0R00V)
R188  ValueDisplayed: 0  [0603]  (hidden comment: ERJ-3GEY0R00V)
R189  ValueDisplayed: 0  [0603]  (hidden comment: ERJ-3GEY0R00V)
R190  ValueDisplayed: 0  [0603]  (hidden comment: ERJ-3GEY0R00V)
R191  ValueDisplayed: 0  [0603]  (hidden comment: ERJ-3GEY0R00V)
R192  ValueDisplayed: 0  [0603]  (hidden comment: ERJ-3GEY0R00V)
R193  ValueDisplayed: 0  [0603]  (hidden comment: ERJ-3GEY0R00V)
R194  ValueDisplayed: 0  [0603]  (hidden comment: ERJ-3GEY0R00V)
R195  ValueDisplayed: 0  [0603]  (hidden comment: ERJ-3GEY0R00V)
R196  ValueDisplayed: 0  [0603]  (hidden comment: ERJ-3GEY0R00V)
R197  ValueDisplayed: 0  [0603]  (hidden comment: ERJ-3GEY0R00V)
R198  ValueDisplayed: 0  [0603]  (hidden comment: ERJ-3GEY0R00V)
R199  ValueDisplayed: 0.1  [0402]  (hidden comment: ERJ2BWFR100X)
R200  ValueDisplayed: 0.1  [0402]  (hidden comment: ERJ2BWFR100X)
R201  ValueDisplayed: 0.1  [0402]  (hidden comment: ERJ2BWFR100X)
S5  CAS-D20TA  [SW_CAS-D20TA]  (value not drawn)
S6  CAS-D20TA  [SW_CAS-D20TA]  (value not drawn)
U1  TMS320F28P650DK9ZEJ  [ZEJ0256A-MFG]  (part A of 4)
U9  TPD6E05U06RVZR  [RVZ0014A]
U20  TPD6E05U06RVZR  [RVZ0014A]
U21  TPD6E05U06RVZR  [RVZ0014A]
U22  TPD6E05U06RVZR  [RVZ0014A]
U23  REF5030AIDR  [D0008A_N]  (parts A,B of 2)
U24  OPA4350EA/250  [DBQ0016A_N]  (parts A,B,C,D,E of 5)

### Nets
GND: C62.2 C63.1 C118.1 C119.1 C120.2 C121.2 C122.2 C123.2 C124.2 C128.2 C129.2 C130.2 C131.2 C132.2 C133.2 C134.2 C135.2 C136.2 C137.2 C138.2 C139.2 C140.2 C141.2 C142.2 C143.2 C144.2 C145.2 C146.2 C147.2 C148.2 C149.2 C150.2 C151.2 U1.L1(VREFLOC) U1.M1(VREFLOA) U1.T4(VREFLOB) U9.5(GND) U9.10(GND) U20.5(GND) U20.10(GND) U21.5(GND) U21.10(GND) U22.5(GND) U22.10(GND) U23.4(GND) U24.13(V-) U24.14(IN_D+) U24.15(IN_D-)
VDDA_3V3: C62.1 C120.1 C124.1 U23.2(VIN) U24.4(V+)
ADC_3V0_REF: S6.6 U23.6(VOUT)
ADC_REF: C123.1 R57.2 U24.3(IN_A+) U24.5(IN_B+) U24.12(IN_C+)
HSEC_ADC-VREFHI: S6.4
HSEC_ADC_A0A1_N: R173.2 U9.2(NC) U9.13(D1-)
HSEC_ADC_A0A1_P: R172.2 U9.1(NC) U9.14(D1+)
HSEC_ADC_A2A3_N: R175.2 U9.4(NC) U9.11(D2-)
HSEC_ADC_A2A3_P: R174.2 U9.3(NC) U9.12(D2+)
HSEC_ADC_A4A5_N: R177.2 U9.7(NC) U9.8(D3-)
HSEC_ADC_A4A5_P: R176.2 U9.6(NC) U9.9(D3+)
HSEC_ADC_A8A9_N: R179.2 U21.4(NC) U21.11(D2-)
HSEC_ADC_A8A9_P: R178.2 U21.3(NC) U21.12(D2+)
HSEC_ADC_A10A11_N: R181.2 U21.7(NC) U21.8(D3-)
HSEC_ADC_A10A11_P: R180.2 U21.6(NC) U21.9(D3+)
HSEC_ADC_A14B14C14A15B15C15_N: R183.2 U20.2(NC) U20.13(D1-)
HSEC_ADC_A14B14C14A15B15C15_P: R182.2 U20.1(NC) U20.14(D1+)
HSEC_ADC_B0B1_N: R185.2 U22.2(NC) U22.13(D1-)
HSEC_ADC_B0B1_P: R184.2 U22.1(NC) U22.14(D1+)
HSEC_ADC_B2B3_N: R187.2 U22.4(NC) U22.11(D2-)
HSEC_ADC_B2B3_P: R186.2 U22.3(NC) U22.12(D2+)
HSEC_ADC_B4B5_N: R189.2 U22.7(NC) U22.8(D3-)
HSEC_ADC_B4B5_P: R188.2 U22.6(NC) U22.9(D3+)
HSEC_ADC_C2C3_N: R191.2 U20.4(NC) U20.11(D2-)
HSEC_ADC_C2C3_P: R190.2 U20.3(NC) U20.12(D2+)
HSEC_ADC_C4: R192.2 U21.2(NC) U21.13(D1-)
HSEC_ADC_C6: R193.2 U21.1(NC) U21.14(D1+)
HSEC_ADC_C10C11_N: R195.2 U20.7(NC) U20.8(D3-)
HSEC_ADC_C10C11_P: R194.2 U20.6(NC) U20.9(D3+)
Int. V_REF: S5.1 S5.4 S6.1
MCU_A0A1_N: C128.1 R173.1 U1.P2(A1)
MCU_A0A1_P: C140.1 R172.1 U1.P1(A0/DACA_OUT)
MCU_A2A3_N: C129.1 R175.1 U1.N4(A3)
MCU_A2A3_P: C141.1 R174.1 U1.N3(A2)
MCU_A4A5_N: C130.1 R177.1 U1.M5(A5)
MCU_A4A5_P: C142.1 R176.1 U1.M4(A4)
MCU_A8A9_N: C131.1 R179.1 U1.T7(A9/GPIO212)
MCU_A8A9_P: C143.1 R178.1 U1.R6(A8/GPIO211)
MCU_A10A11_N: C132.1 R181.1 U1.R8(A11/GPIO214)
MCU_A10A11_P: C144.1 R180.1 U1.T8(A10/GPIO213)
MCU_A14B14C14A15B15C15_N: C133.1 R183.1 U1.R2(A15/B15/C15)
MCU_A14B14C14A15B15C15_P: C145.1 R182.1 U1.R1(A14/B14/C14)
MCU_B0B1_N: C134.1 R185.1 U1.T3(B1/DACC_OUT)
MCU_B0B1_P: C146.1 R184.1 U1.T2(B0/VDAC)
MCU_B2B3_N: C135.1 R187.1 U1.P3(B3)
MCU_B2B3_P: C147.1 R186.1 U1.R3(B2)
MCU_B4B5_N: C136.1 R189.1 U1.N7(B5/GPIO216)
MCU_B4B5_P: C148.1 R188.1 U1.P7(B4/GPIO215)
MCU_C2C3_N: C137.1 R191.1 U1.L5(C3/GPIO206)
MCU_C2C3_P: C149.1 R190.1 U1.L4(C2)
MCU_C4: C150.1 R192.1 U1.M6(C4/GPIO205)
MCU_C6: C138.1 R193.1 U1.K5(C6/GPIO203)
MCU_C10C11_N: C139.1 R195.1 U1.K2(C11)
MCU_C10C11_P: C151.1 R194.1 U1.L3(C10)
NetC63_2: C63.2 R199.1
NetC118_2: C118.2 R200.1
NetC119_2: C119.2 R201.1
NetC121_1: C121.1 U23.5(TRIM/NR)
NetC122_1: C122.1 R57.1 S6.5(C)
NetR196_1: R196.1 S6.2(C)
NetR196_2: R196.2 R199.2 U1.M2(VREFHIA)
NetR197_1: R197.1 S5.5(C)
NetR197_2: R197.2 R200.2 U1.R4(VREFHIB)
NetR198_1: R198.1 S5.2(C)
NetR198_2: R198.2 R201.2 U1.L2(VREFHIC)
NetS5_3: S5.3 U24.10(OUT_C) U24.11(IN_C-)
NetS5_6: S5.6 U24.6(IN_B-) U24.7(OUT_B)
NetS6_3: S6.3 U24.1(OUT_A) U24.2(IN_A-)

Not connected (* = marked no-connect by the designer): U1 H1(C0/GPIO199)* J1(C1/GPIO200)* J2(C9/GPIO201)* K1(C13)* K3(C8/GPIO202)* K4(C7/GPIO198)* L6(C5/GPIO204)* N5(B6/GPIO207)* N6(A6/GPIO209)* N8(B9/GPIO218)* P4(B11)* P5(B7/GPIO208)* P6(A7/GPIO210)* P8(B8/GPIO217)* R5(B13)* R7(B10/GPIO219)*; U23 1(DNC)* 3(TEMP)* 7(NC)* 8(DNC)*; U24 8(NC)* 9(NC)* 16(OUT_D)*

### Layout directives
differential pair: HSEC_ADC_A0A1_N, HSEC_ADC_A0A1_P, HSEC_ADC_A2A3_N, HSEC_ADC_A2A3_P, HSEC_ADC_A4A5_N, HSEC_ADC_A4A5_P, HSEC_ADC_A8A9_N, HSEC_ADC_A8A9_P, HSEC_ADC_A10A11_N, HSEC_ADC_A10A11_P, HSEC_ADC_A14B14C14A15B15C15_N, HSEC_ADC_A14B14C14A15B15C15_P, HSEC_ADC_B0B1_N, HSEC_ADC_B0B1_P, HSEC_ADC_B2B3_N, HSEC_ADC_B2B3_P, HSEC_ADC_B4B5_N, HSEC_ADC_B4B5_P, HSEC_ADC_C2C3_N, HSEC_ADC_C2C3_P, HSEC_ADC_C10C11_N, HSEC_ADC_C10C11_P, MCU_A0A1_N, MCU_A0A1_P, MCU_A2A3_N, MCU_A2A3_P, MCU_A4A5_N, MCU_A4A5_P, MCU_A8A9_N, MCU_A8A9_P, MCU_A10A11_N, MCU_A10A11_P, MCU_A14B14C14A15B15C15_N, MCU_A14B14C14A15B15C15_P, MCU_B0B1_N, MCU_B0B1_P, MCU_B2B3_N, MCU_B2B3_P, MCU_B4B5_N, MCU_B4B5_P, MCU_C2C3_N, MCU_C2C3_P, MCU_C10C11_N, MCU_C10C11_P
50 Ohm Impedance: Undefined: GND, HSEC_ADC_A0A1_N, HSEC_ADC_A0A1_P, HSEC_ADC_A2A3_N, HSEC_ADC_A2A3_P, HSEC_ADC_A4A5_N, HSEC_ADC_A4A5_P, HSEC_ADC_A8A9_N, HSEC_ADC_A8A9_P, HSEC_ADC_A10A11_N, HSEC_ADC_A10A11_P, HSEC_ADC_A14B14C14A15B15C15_N, HSEC_ADC_A14B14C14A15B15C15_P, HSEC_ADC_B0B1_N, HSEC_ADC_B0B1_P, HSEC_ADC_B2B3_N, HSEC_ADC_B2B3_P, HSEC_ADC_B4B5_N, HSEC_ADC_B4B5_P, HSEC_ADC_C2C3_N, HSEC_ADC_C2C3_P, HSEC_ADC_C4, HSEC_ADC_C6, HSEC_ADC_C10C11_N, HSEC_ADC_C10C11_P, MCU_A0A1_N, MCU_A0A1_P, MCU_A2A3_N, MCU_A2A3_P, MCU_A4A5_N, MCU_A4A5_P, MCU_A8A9_N, MCU_A8A9_P, MCU_A10A11_N, MCU_A10A11_P, MCU_A14B14C14A15B15C15_N, MCU_A14B14C14A15B15C15_P, MCU_B0B1_N, MCU_B0B1_P, MCU_B2B3_N, MCU_B2B3_P, MCU_B4B5_N, MCU_B4B5_P, MCU_C2C3_N, MCU_C2C3_P, MCU_C4, MCU_C6, MCU_C10C11_N, MCU_C10C11_P

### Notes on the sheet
- S6 (POS 2)
- 1
- Ext. V_REF Selection
- HSEC_ADC-VREFHI
- ADC_REF
- 0
- Voltage reference Configuration Switch Truth Table
- ADC_3V0_REF (DEFAULT)
- NOTE: “The reference pins, VREFHIA to VREFHIC and VREFLOA to VREFLOC, can be used to supply an external voltage reference to the associated ADCs. VREFHIA can also be used to supply the voltage reference to DAC A, and VREFHIB can be used to supply the voltage reference to DAC C. An internal voltage reference is available and connects to VREFHIA. To use the internal voltage reference on ADC B, ADC C or DAC C, connect VREFHIA to VREFHIB and/or VREFHIC externally.”
- S6 (POS 1)
- S5 (POS 1)
- S5 (POS 2)
- Int. V_REF
- C2000 ADC V_REF
- DESCRIPTION
- NC - No reference input
- Ext. V_REF
- Place near U1
- (near S6) (POS 1)
- (near S6) S6 Switch
- (near S6) (POS 2)
- (near S5) (POS 1)
- (near S5) S5 Switch
- (near S5) (POS 2)
- (near U24) Unused OP-AMP
- ADC_A0A1_P and ADC_A0A1_N make a differential pair using channels A0 and A1 respectivly.
  If you wish to use A0 or A1 independently the "_P" refers to the first ADC channel (For example A0 in "ADC_A0A1"). Additionally the "_N" refers to the second channel, (A1 in "ADC_A0A1").
  NOTE: C6 and C4 are not differential pairs

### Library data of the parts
C62 C124 = CMP-0006829-4: CAP, CERM, 0.1 uF, 16 V, +/- 10%, X7R, 0603; Manufacturer: Wurth Elektronik; TaMin_C: -55°C; Polarized: N; SizeAreaWB_mm2: 4.68; Value1: Unknown; U/M: EA; Value: 0.1uF; TaMax_C: 125°C; SizeZ_mm: 1; SizeX_mm: 1.6; SizeY_mm: 0.8; Value2: 16V; SizeArea_mm2: 1.28; AEC Category: Q200
C63 C118 C119 = CMP-0097305-1: 4.7 µF ±20% 10V Ceramic Capacitor X5R 0603 (1608 Metric); Manufacturer: Wurth Electronics; Cap_F: 4.7µF; Value: 4.7µF; AEC Qualified: No; SizeZ_mm: 0.87mm; TempCo: 15%
C120 = CMP-0006825-5: CAP, CERM, 2.2 uF, 16 V, +/- 20%, X5R, 0603; Manufacturer: Wurth Elektronik; TaMin_C: -55°C; Polarized: N; SizeAreaWB_mm2: 4.68; Value1: Unknown; U/M: EA; Value: 2.2uF; TaMax_C: 85°C; SizeZ_mm: 1; SizeX_mm: 1.6; SizeY_mm: 0.8; Value2: 16V; SizeArea_mm2: 1.28; Cap_F: 2.2µF; AEC Category: Q200
C121-C123 = CMP-0006831-4: CAP, CERM, 1 uF, 16 V, +/- 10%, X7R, 0603; Manufacturer: Wurth Elektronik; TaMin_C: -55°C; Polarized: N; SizeAreaWB_mm2: 4.68; Value1: Unknown; U/M: EA; Value: 1uF; TaMax_C: 125°C; SizeZ_mm: 1; SizeX_mm: 1.6; SizeY_mm: 0.8; Value2: 16V; SizeArea_mm2: 1.28; AEC Category: Q200
C128-C151 = CMP-0006920-4: CAP, CERM, 330 pF, 50 V, +/- 5%, C0G/NP0, 0603; Manufacturer: Kemet; TaMin_C: -55°C; Polarized: N; SizeAreaWB_mm2: 4.68; Value1: Unknown; U/M: EA; Value: 330pF; TaMax_C: 125°C; SizeZ_mm: 1; SizeX_mm: 1.6; SizeY_mm: 0.8; Value2: 50V; SizeArea_mm2: 1.28; AEC Category: Q200
R57 = CMP-0022895-5: RES, 1.00 k, 1%, 0.1 W, 0603; Manufacturer: Yageo; Power_W: 100mW; TempCo: 100 ppm/C; Value_Code: 1k00; Value: 1.00k; EIA_Code: E96; Res_ohm: 1k; SizeX_mm: 1.6; SizeY_mm: 0.8; SizeZ_mm: 1; Value2: 0.1W; SizeArea_mm2: 1.28; AEC Qualified: N; VDC_V: 75V; AEC Category: Q200; SizeAreaWB_mm2: 4.68
R172-R198 = CMP-0025874-4: as R33 on sheet MCU114B_Support
R199-R201 = CMP-0078660-1: RES, 0.1, 1%, 0.25 W, 0402; Manufacturer: Panasonic; Power_W: 250mW; TempCo: 300 ppm/C; Value_Code: R100; Value: 0.1; EIA_Code: E96; SizeX_mm: 1; SizeY_mm: 0.5; SizeZ_mm: 0.6; Value2: 0.25W; AEC Qualified: N; AEC Category: Q200
S5 S6 = CMP-0002233-1: as S2 on sheet MCU114B_Support
U1 = CMP-0096042-2: as U1 on sheet MCU114B_GPIOs
U9 U20-U22 = CMP-0073614-1: 6-Channel Ultra-Low-Capacitance IEC ESD Protection Diodes, RVZ0014A (USON-14); Alternate Manufacturer: Texas Instruments; Green_Lifecycle: Active; SizeAreaWB_mm2: 10.575; Green_REACh: Passed; U/M: EA; SizeZ_mm: 0.55; SizeX_mm: 1.35; SizeY_mm: 3.5; SizeArea_mm2: 4.725; CompType: IC
U23 = CMP-0032592-1: Low Noise, Very Low Drift, Precision Voltage Reference, -40 to 125 degC, 8-pin SOIC (D), Green (RoHS & no Sb/Br); Manufacturer: Texas Instruments; Iq(Max)(uA): 1000; SubFamily: Series Voltage Reference; Temp Coeff(Max)(ppm/ degree C): 3; VI(Min)(V): 3.2; Rating: Catalog; Initial Accuracy @ 25/deg C(%): 0.05; VI(Max)(V): 18; Iout/Iz(Max)(mA): 10
U24 = CMP-0041147-1: High-Speed, Single-Supply, Rail-to-Rail Operational Amplifier MicroAmplifier(TM) Series, 2.7 to 5.5 V, -55 to 150 degC, 16-pin SOP (DBQ16), Green (RoHS & no Sb/Br); Manufacturer: Texas Instruments; Number of Channels: 4; Vio (25C)(Max)(mV): 0.5; Total Supply Voltage(Min)(+5V is 5, +/-5V is 10): 2.7; Slew Rate(Typ)(V/us): 22; Total Supply Voltage(Max)(+5V is 5, +/-5V is 10): 5.5; Iq per channel(Max)(mA): 7.5; Vn at 1kHz(Typ)(nV/rtHz): 18; Sub Family: Low Input Bias Current Amp (<=10pA), Low Offset Voltage Amplifier (<=500uV), Low Supply Voltage Amplifier (<=2.7V), Precision Amplifier; IIB(Max)(pA): 10; CMRR(Min)(dB): 66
